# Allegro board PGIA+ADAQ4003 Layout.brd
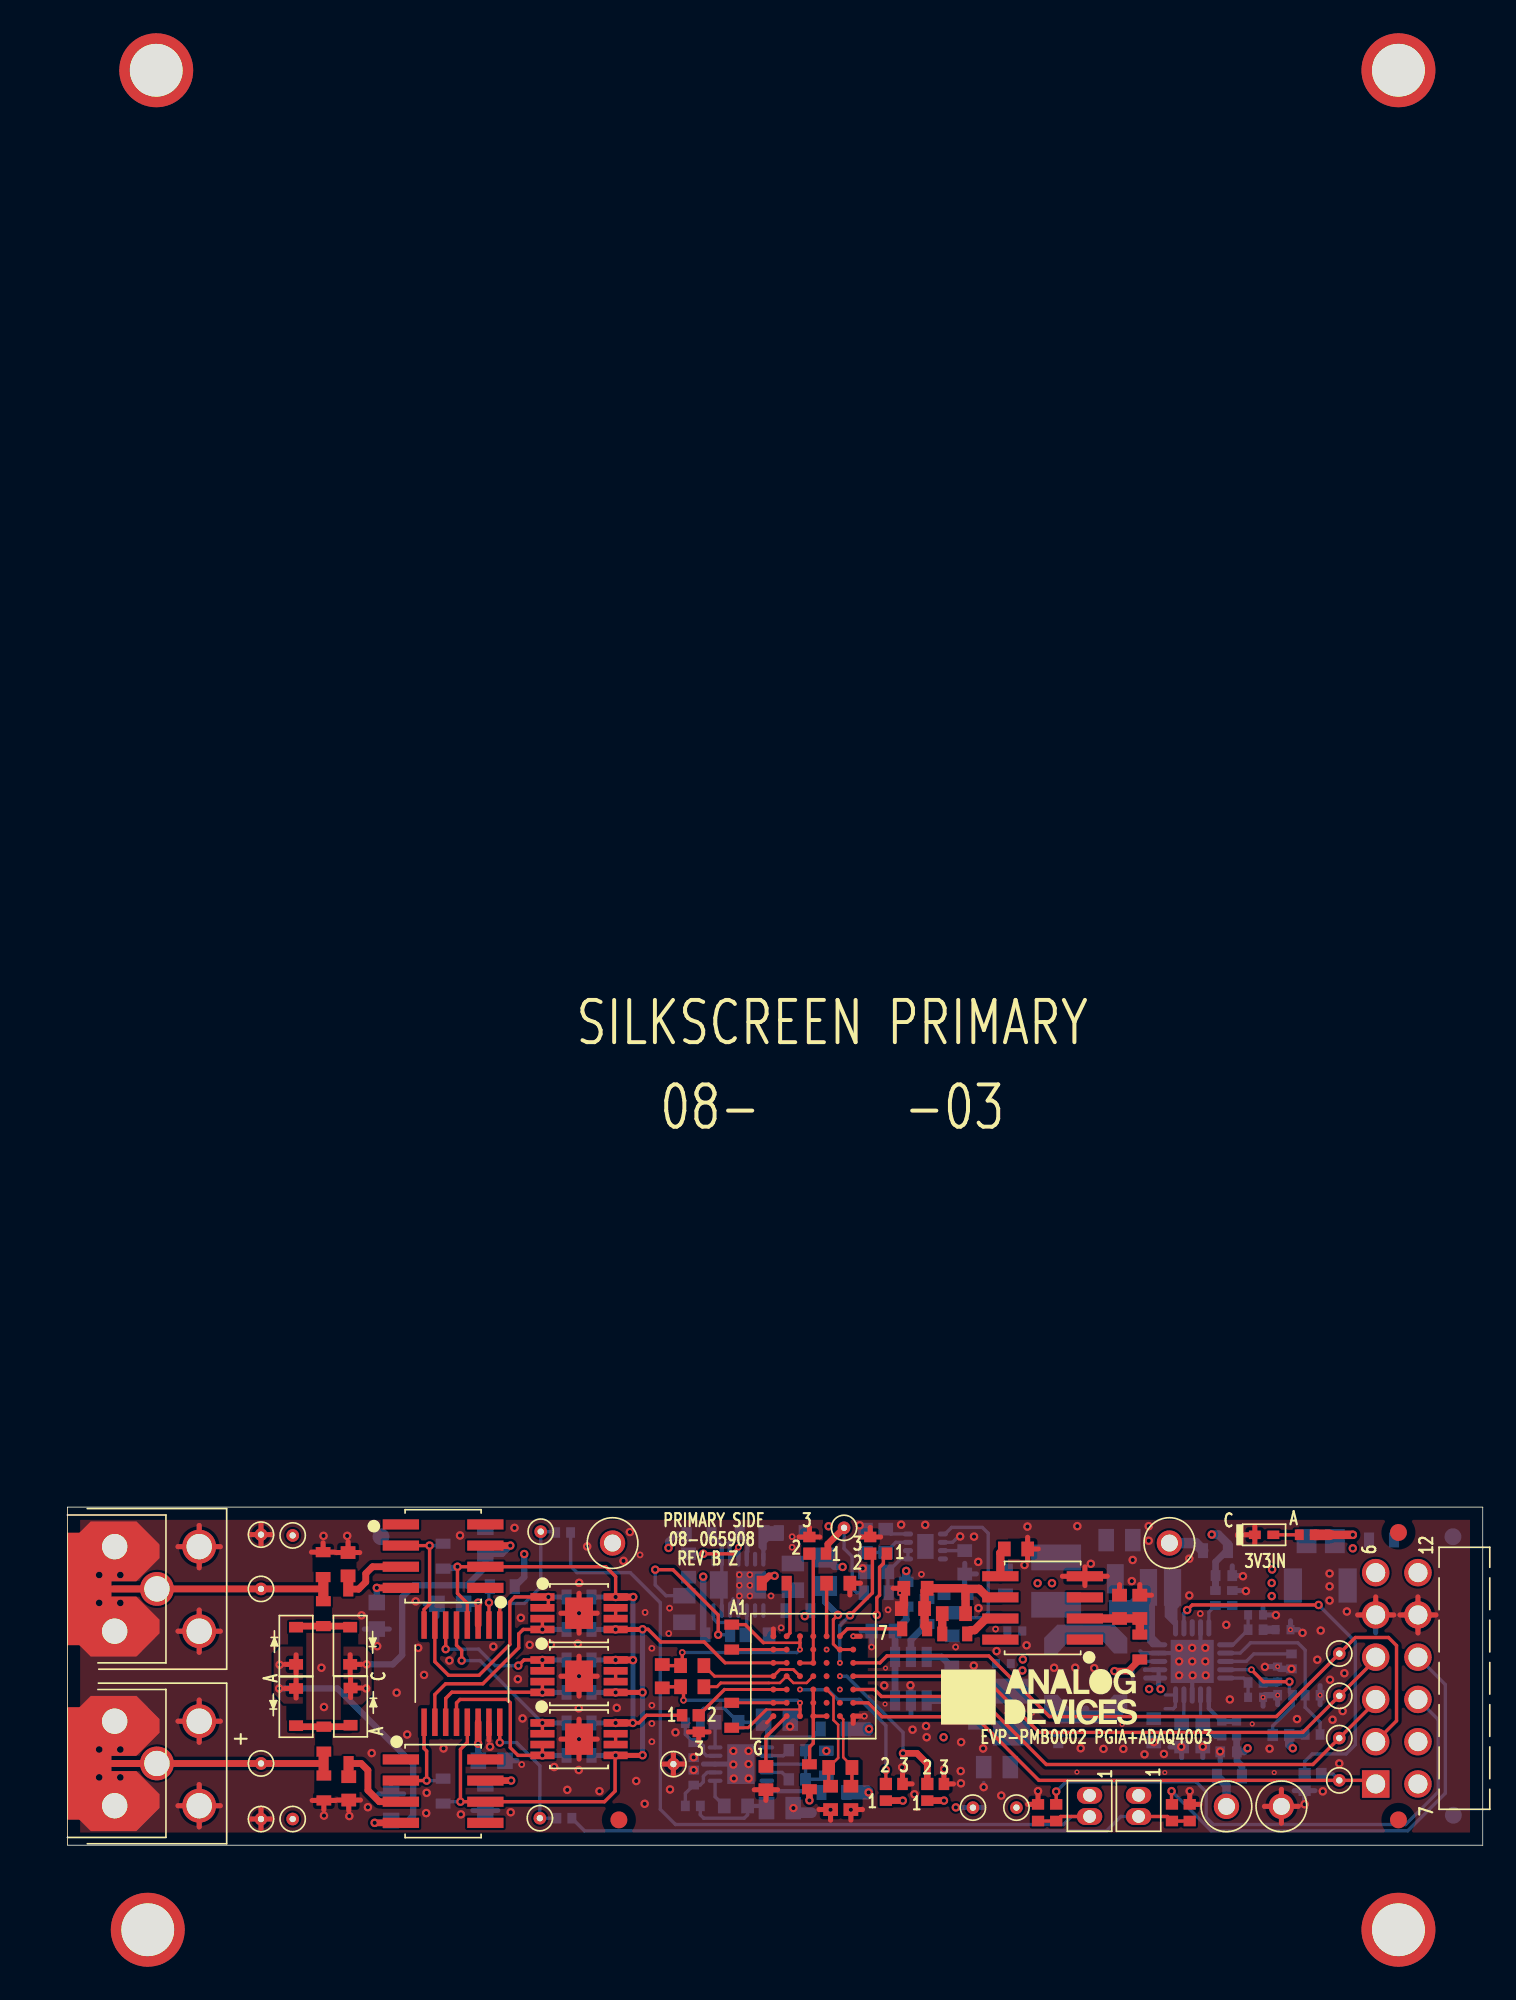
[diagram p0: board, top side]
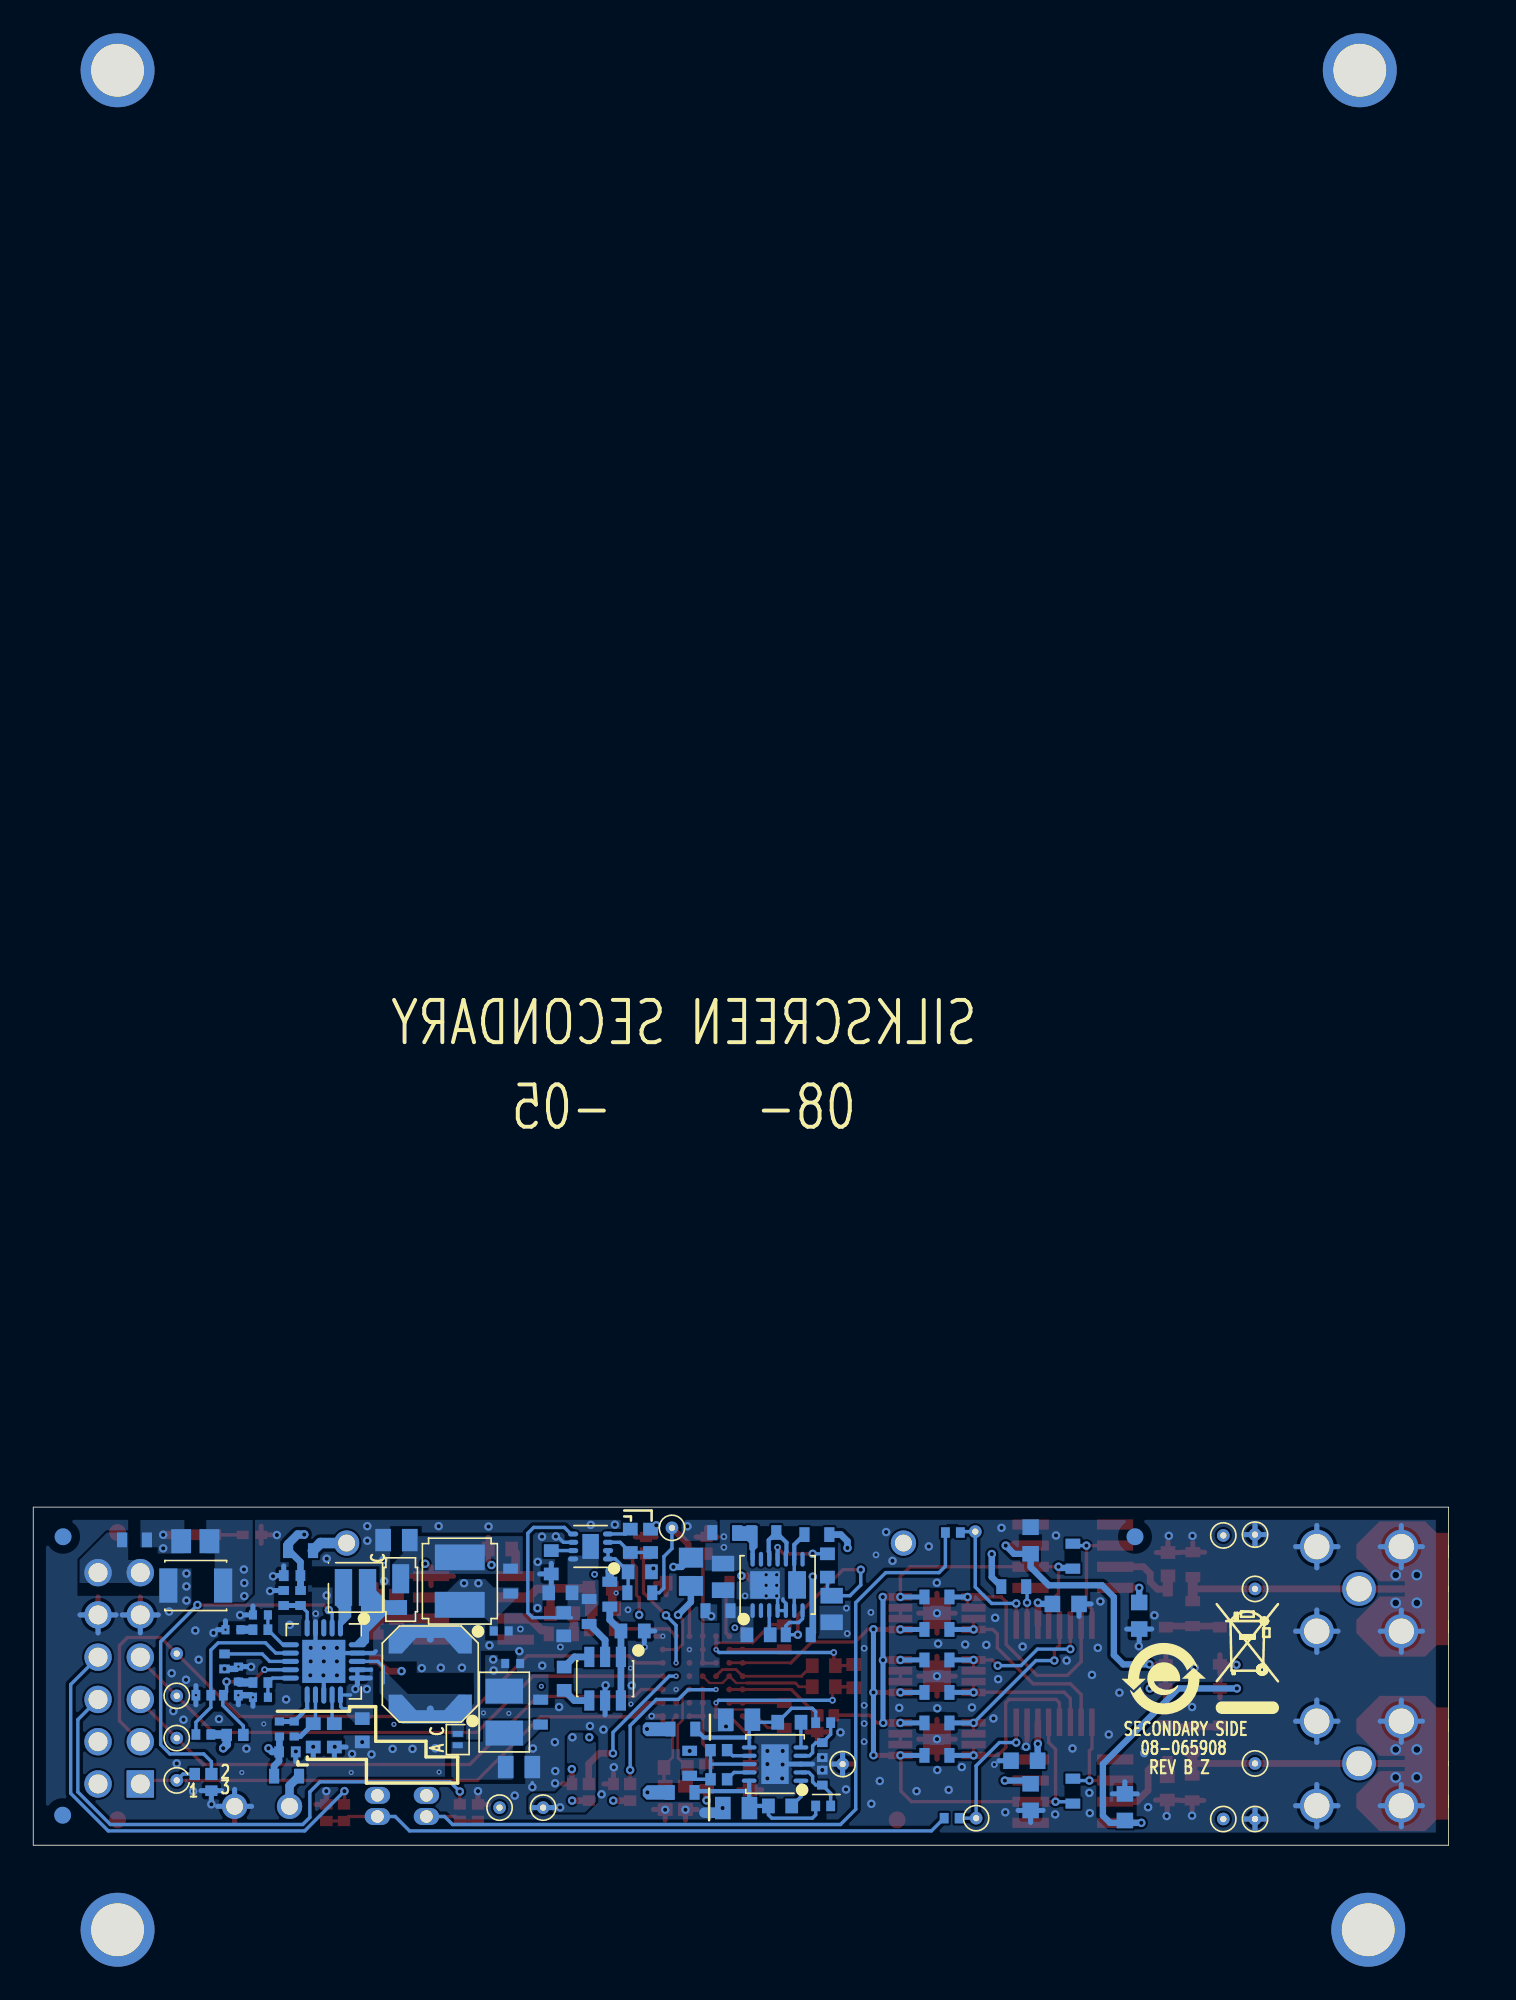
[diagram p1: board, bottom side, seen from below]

Outline 85.08 x 20.32 mm; copper layers: TOP, L2_GND, L3_PWR, BOTTOM. Coordinates in mm from the lower left corner of the outline.
Outline path: 0,20.32 0,0 85.08,0 85.08,20.32 0,20.32

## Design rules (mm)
constraint set DEFAULT: min track width 0.203

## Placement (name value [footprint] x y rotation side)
A1  ADA4627-1BRZ  [SO8]  22.58 17.37 270 top
A2  ADA4627-1BRZ  [SO8]  22.58 3.25 270 top
C1  2.2uF  [C0603]  64.46 14.33 90 top
C2  0.1uF  [C0603]  63.24 14.33 90 top
C3  TBD0603  [C0603]  57.02 17.81 0 top
C4  TBD0603  [C0603]  53.29 13.92 0 top
C5  22uF  [C1210H106]  75.31 15.61 180 bottom
C6  0.1uF  [C0603]  50.98 15.44 180 top
C7  1uF  [C0603]  66.98 6.6 90 bottom
C8  2.2uF  [C0603]  50.83 14.22 180 top
C9  10uF  [C0603]  65.3 6.91 90 bottom
C10  TBD0603  [C0603]  46.33 15.75 0 top
C11  TBD0603  [C0603]  41.99 4.04 270 top
C12  0.01uF  [C0603]  39.62 7.39 180 bottom
C13  0.01uF  [C0603]  40.18 2.36 180 bottom
C14  0.01uF  [C0603]  41.48 12.65 0 bottom
C15  0.01uF  [C0603]  37.34 16.81 270 bottom
C16  4.7uF  [C0805H60]  43.61 16.13 90 bottom
C17  4.7uF  [C0805H60]  37.08 14.2 90 bottom
C18  4.7uF  [C0805H60]  42.65 7.54 0 bottom
C19  4.7uF  [C0805H60]  42.82 2.24 0 bottom
C20  TBD0603  [C0603]  16.87 16.89 90 top
C21  TBD0603  [C0603]  16.91 3.42 270 top
C22  0.1uF  [C0603#2]  25.5 5.08 0 bottom
C23  TBD0603  [R0603]  22.58 17.37 270 bottom
C24  TBD0603  [R0603]  22.58 3.25 270 bottom
C25  0.1uF  [C0603#2]  18.59 13.79 270 bottom
C26  TBD0603  [C0603]  35.75 10.16 270 top
C27  0.1uF  [C0603#2]  23.01 14.5 180 bottom
C28  1uF  [C0603]  68.25 6.6 270 bottom
C29  0.1uF  [C0603#2]  25.12 18.31 90 bottom
C30  TBD0603  [R0603]  30.75 14.92 0 bottom
C31  TBD0603  [R0603]  30.75 12.97 0 bottom
C32  TBD0603  [C0603]  37.56 10.79 0 top
C33  TBD0603  [C0603]  37.56 9.53 0 top
C34  TBD0603  [R0603]  30.75 9.18 0 bottom
C35  TBD0603  [R0603]  30.75 11.14 0 bottom
C36  TBD0603  [R0603]  30.75 5.4 0 bottom
C37  TBD0603  [C0603]  47.09 2.84 270 top
C38  TBD0603  [R0603]  30.75 7.35 0 bottom
C39  TBD0603  [C0603]  46.46 4.67 180 top
C40  TBD0603  [C0603]  45.87 2.84 270 top
C41  TBD0402  [C0402#2]  69.52 16.21 180 bottom
C42  TBD0402  [C0402#2]  69.8 5.61 0 bottom
C43  4.7uF  [C0603]  48.62 16.43 180 bottom
C44  10uF  [C0805H60]  55.88 4.7 0 bottom
C45  1uF  [C0603]  47.97 18.3 90 bottom
C46  10uF  [C0603]  49.05 12.88 0 bottom
C47  10uF  [C0805H60]  63.24 18.34 180 bottom
C48  0.01uF  [C0603]  49.19 18.3 90 bottom
C49  1uF  [C0603]  53.16 10.01 270 bottom
C50  10uF  [C0603]  53.19 13.28 90 bottom
C51  27pF  [C0402H22]  71.42 13.84 0 bottom
C52  47pF  [C0402]  71.42 8.89 0 bottom
C53  4.7uF  [C0603]  53.39 15.18 0 bottom
C54  1500pF  [C0402]  73.07 12.95 0 bottom
C55  0.022uF  [C0402]  72.74 10.29 90 bottom
C56  1uF  [C0603]  53.94 17.01 270 bottom
C57  TBD0402  [C0402]  56.26 10.92 180 bottom
C58  TBD0402  [C0402]  56.94 12.88 0 bottom
C61  0.1uF  [C0603#2]  25.12 2.9 270 bottom
C62  0.1uF  [C0603#2]  19.46 2.29 90 bottom
CNV  TESTPAD  [TPC30D15]  76.45 3.9 0 top
D1  PD3S140-7  [POWERDI323]  62.99 15.37 270 bottom
D2  BAT54LPS  [DFN2_1X0_6]  59.56 6.35 270 bottom
D3  NSR0320MW2T1G  [SOD323-4]  16.99 11.99 90 top
D4  NSR0320MW2T1G  [SOD323-4]  13.74 11.99 270 top
D5  NSR0320MW2T1G  [SOD323-4]  17.02 8.33 270 top
D6  NSR0320MW2T1G  [SOD323-4]  13.74 8.31 90 top
DS1  APHHS1005CGCK  [LED0402_A]  71.93 18.66 0 top
E1  600OHM AT 100MEGHZ  [L0805]  45.54 16.43 90 bottom
E2  600OHM AT 100MEGHZ  [L0805]  75.34 18.28 180 bottom
GND1  TESTPAD  [TPC30D15]  11.63 1.57 0 top
GND2  TESTPAD  [TPC30D15]  11.63 18.67 0 top
GND3  TESTPAD  [TPC30D15]  36.42 4.88 0 top
J1  131-3701-301  [CNJOHNSON131-3701-301]  5.38 15.41 0 top
J2  131-3701-301  [CNJOHNSON131-3701-301]  5.38 4.91 0 top
J3  142-0761-841  [CNSMAL554W247H118]  0 15.4 180 top
J4  142-0761-841  [CNSMAL554W247H118]  0 4.91 180 top
JA0  FTS-102-01-F-S  [CNSAMTECFTS-102-01-F-S]  61.44 3 270 top
JA1  FTS-102-01-F-S  [CNSAMTECFTS-102-01-F-S]  64.39 3 270 top
JP1  3PIN_JUMPER  [3PINJUMPER_0402]  74.37 4.28 90 bottom
JP2  3PIN_JUMPER  [3PINJUMPER_0402]  37.95 7.81 90 top
JP3  3PIN_JUMPER  [3PINJUMPER_0402]  51.69 3.68 180 top
JP4  3PIN_JUMPER  [3PINJUMPER_0402]  48.26 17.53 270 top
JP5  3PIN_JUMPER  [3PINJUMPER_0402]  49.2 3.68 180 top
JP6  3PIN_JUMPER  [3PINJUMPER_0402]  44.6 17.53 270 top
L1  4.7uH  [LSMSQ79H57]  65.71 15.49 180 bottom
L2  33UH  [LSMSQ189H123]  61.21 10.29 270 bottom
L3  1.5uH  [L2520-3]  56.77 8 90 bottom
L4  2.2UH  [L1515]  59.43 15.87 270 bottom
N1V  TESTPAD  [TPC30D15]  46.68 19.08 0 top
N15V  TESTPAD  [TPC30D15]  13.54 18.62 0 top
N16V  RED  [CNKEY5001TP]  69.67 2.34 0 top
NOREF  -  []  63.44 -165.56 0 top
NOREF#2  -  []  4.83 -5.08 0 top
NOREF#3  -  []  0 20.59 0 top
NOREF#4  -  []  4.83 -5.08 0 top
NOREF#5  -  [unnamed#2]  80.01 1.52 0 top
NOREF#6  -  []  85.06 -6.73 90 top
NOREF#7  -  []  0 20.32 0 top
NOREF#8  -  []  -20.7 -48.64 0 top
NOREF#9  -  []  85.09 -10.16 90 top
NOREF#10  -  []  85.09 -10.16 0 top
NOREF#11  -  []  0 0 0 top
NOREF#12  -  []  0 40.86 0 top
NOREF#13  -  []  0 -0.03 0 top
NOREF#14  -  []  0 101.78 0 top
NOREF#15  -  []  -218.18 -201.45 0 top
NOREF#16  -  []  0 60.63 0 top
NOREF#17  -  [unnamed#2]  33.15 1.52 0 top
NOREF#18  -  [unnamed#2]  80.01 -5.08 0 top
NOREF#19  -  [unnamed#2]  4.83 -5.08 0 top
NOREF#20  -  []  0 20.58 0 top
NOREF#21  -  []  162.43 50.2 0 top
NOREF#22  -  []  0 111.76 0 top
NOREF#23  -  []  0 60.96 0 top
NOREF#24  -  []  0 111.76 0 top
NOREF#25  -  []  268.73 -83.5 0 top
NOREF#26  -  [unnamed#2]  80.01 18.8 0 top
NOREF#27  -  []  0 101.6 0 top
NOREF#28  -  []  0 81.33 0 top
NOREF#29  -  [unnamed#2]  80.01 106.68 0 top
NOREF#30  -  []  -28.18 -217.58 0 top
NOREF#31  -  []  60.96 159.38 0 top
NOREF#32  -  []  0 -10.16 0 top
NOREF#33  -  []  45.97 43.21 0 top
NOREF#34  -  []  0 -10.16 0 top
NOREF#35  -  [unnamed#2]  5.33 106.68 0 top
NOREF#36  -  []  0 40.64 0 top
NOREF#37  -  []  58.42 8.05 0 top
NOREF#38  -  []  -4.83 25.91 270 top
NOREF#39  -  []  90.16 22.21 180 top
NOREF#40  -  []  0 81.28 0 top
NOREF#41  -  []  0 10.11 0 top
NOREF#42  -  []  -7.05 -8.13 0 top
NOREF#43  -  [unnamed#2]  83.31 1.8 180 bottom
NOREF#44  -  []  17.12 10.01 180 bottom
NOREF#45  -  [unnamed#2]  18.85 18.54 180 bottom
NOREF#46  -  []  12.29 7.95 180 bottom
NOREF#47  -  [unnamed#2]  83.29 18.54 180 bottom
P1  TSW-106-25-F-D-RA  [CNHDRRA2X6H240]  78.64 3.68 90 top
P15V  TESTPAD  [TPC30D15]  13.54 1.57 0 top
P16V  RED  [CNKEY5001TP]  66.24 18.16 0 top
R1  0  [R0603]  64.46 11.91 90 top
R2  0  [R0603]  78.99 18.35 180 bottom
R3  TBD0603  [R0603]  53.34 12.7 180 top
R4  0  [R0603]  50.93 13 180 top
R5  100K  [R0402]  58.34 1.96 270 top
R6  10K  [R0402]  59.44 1.96 270 top
R7  100K  [R0402]  67.46 1.96 270 top
R8  0  [R0603]  42.48 15.75 0 top
R9  0  [R0603]  15.38 13.92 270 top
R10  0  [R0603]  15.41 6.38 90 top
R11  0  [R0603]  44.6 4.11 270 top
R12  10K  [R0402]  66.4 1.96 270 top
R13  0  [R0603]  45.62 4.93 270 bottom
R14  0  [R0603]  43.51 18.8 180 bottom
R15  0  [R0603]  37.97 18.67 0 bottom
R16  0  [R0402]  43.87 5.71 180 bottom
R17  0  [R0402]  43.87 3.96 180 bottom
R18  0  [R0603]  41.16 18.8 180 bottom
R19  698K  [R0402#2]  37.59 7.37 180 bottom
R20  200K  [R0402#2]  37.64 5.71 270 bottom
R21  0  [R0603]  43.91 14.1 0 bottom
R22  0  [R0603]  39.09 12.65 180 bottom
R23  95.3K  [R0402#2]  37.59 2.36 180 bottom
R24  1MEG  [R0603]  15.37 16.87 90 top
R25  1MEG  [R0603]  15.41 3.44 270 top
R26  200  [R0603]  16.13 15.39 0 top
R27  200  [R0603]  16.15 4.91 0 top
R28  10K  [R0603]  26.14 15.54 0 bottom
R29  200K  [R0402#2]  37.64 4.06 90 bottom
R30  0  [R0402#2]  29.79 18.8 0 bottom
R31  0  [R0402#2]  29.87 1.63 0 bottom
R32  0  [R0603]  39.93 12.51 270 top
R33  0  [R0603]  39.93 7.81 90 top
R34  2.4K  [R0402#2]  74.5 18.66 180 top
R35  30.1K  [R0402]  72.95 6.63 180 bottom
R36  18.7K  [R0402#2]  73.2 9.02 180 bottom
R37  0  [R0603]  46.02 6.98 0 bottom
R38  0  [R0603]  46.08 3.18 0 bottom
R39  0  [R0603]  54.58 8 90 bottom
R40  0  [R0603]  50.42 15.09 270 bottom
R41  249K  [R0402#2]  73.58 11.05 90 bottom
R42  3.09K  [R0402#2]  69.39 6.98 270 bottom
R43  0  [R0603]  48.62 15.18 0 bottom
R44  0  [R0603]  51.66 14.05 90 bottom
R52  12.4K  [R0402#2]  71.42 12.95 0 bottom
R53  64.9K  [R0402#2]  70.28 6.98 270 bottom
R54  3.57K  [R0402#2]  70.03 14.86 270 bottom
R55  7.68K  [R0402#2]  71.42 9.78 0 bottom
R58  68.1K  [R0402#2]  69.01 14.86 90 bottom
R60  0  [R0603]  56.39 15.87 270 bottom
R65  0  [R0603]  69.01 17.7 180 bottom
R66  0  [R0603]  69.85 4.15 180 bottom
R80  30.1K  [R0402#2]  74.85 6.65 0 bottom
R81  18.7K  [R0402#2]  74.85 9.02 0 bottom
RN1  1K/9K  [MSOP8_PAD1_88X1_68]  30.75 13.94 270 top
RN2  1K  [MSOP8_PAD1_88X1_68]  30.75 6.38 270 top
RN3  1.25K/5K  [MSOP8_PAD1_88X1_68]  30.75 10.16 270 top
SCK  TESTPAD  [TPC30D15]  76.45 8.98 0 top
SDI  TESTPAD  [TPC30D15]  76.45 11.52 0 top
SDO  TESTPAD  [TPC30D15]  76.45 6.44 0 top
TP3  BLK  [CNKEY5001TP]  72.97 2.34 0 top
TP_A0  TESTPAD  [TPC30D15]  28.45 18.85 0 top
TP_A1  TESTPAD  [TPC30D15]  28.4 1.63 0 top
U1  ADR4550BRZ  [SO8]  58.62 14.26 90 top
U2  ADAQ4003BBCZ  [BGA49H96]  44.83 10.16 270 top
U3  LT3023IDD#PBF  [DFN10_3X3_PAD2_38X1_64]  40.49 4.88 90 bottom
U4  ADP5070ACPZ-R7  [QFN20_4X4_PAD2_6X2_6]  67.61 11.05 0 bottom
U5  ADG1209YRUZ  [TSSOP16]  23.71 10.31 180 top
U6  LTC1983ES6-3#PBF  [TSOT23_6]  50.7 10.01 0 bottom
U7  ADP7185ACPZN1.0  [DFN8_2X2_PAD1_5X1]  51.57 17.96 90 bottom
U8  LT3032EDE-15#PBF  [DFN14_4X3_PAD1_78X1_65_PAD1_07X1_65]  40.33 15.65 180 bottom
UNK1V8  TESTPAD  [TPC30D15]  54.43 2.26 0 top
UNK3V3_EX  RED  [CNKEY5001TP]  32.77 18.16 0 top
UNK5V5  TESTPAD  [TPC30D15]  57.05 2.26 0 top
VIN+  TESTPAD  [TPC30D15]  11.63 4.91 0 top
VIN-  TESTPAD  [TPC30D15]  11.63 15.41 0 top

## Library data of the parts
A1 A2 = ADA46X7: Tolerance: N/A; User Part Number: UPN; alternate symbols: (); part number: ADA46X7_SM-ADA4627-1BRZ,E028104,SO8; tolerance: N/A
C1 C8 = CAP: User Part Number: UPN; Tolerance: 10; alternate symbols: C0603L; part number: CAP_SM-2.2UF,50V,10,E024995,C0603; tolerance: 10
C2 C6 = CAP: User Part Number: UPN; Tolerance: 10; alternate symbols: C0603L; part number: CAP_SM-0.1UF,50V,10,E011865,C0603; tolerance: 10
C3 C4 C10 C11 C26 C32 C33 C37 C39 C40 = CAP: User Part Number: UPN; alternate symbols: C0603L; part number: CAP_SM-TBD0603,TBD0603,TBD0603,E000382,C0603
C5 = CAP: Tolerance: 20; User Part Number: UPN; alternate symbols: (); part number: CAP_SM-22UF,25V,20,E038599,C1210H106; tolerance: 20
C7 C28 C45 C49 C56 = CAP: User Part Number: UPN; Tolerance: 10; alternate symbols: C0603L; part number: CAP_SM-1UF,16V,10,E020111,C0603; tolerance: 10
C9 = CAP: User Part Number: UPN; Tolerance: 20; alternate symbols: C0603L; part number: CAP_SM-10UF,6.3V,20,E030255,C0603; tolerance: 20
C12-C15 C48 = CAP: User Part Number: UPN; Tolerance: 5; alternate symbols: C0603L; part number: CAP_SM-0.01UF,25V,5,E012400,C0603; tolerance: 5
C16 C17 = CAP: User Part Number: UPN; Tolerance: 10; alternate symbols: C0805L; part number: CAP_SM-4.7UF,35V,10,E026260,C0805H60; tolerance: 10
C18 C19 = CAP: User Part Number: UPN; Tolerance: 10; alternate symbols: C0805L; part number: CAP_SM-4.7UF,16V,10,E033932,C0805H60; tolerance: 10
C20 C21 = CAP: User Part Number: UPN; alternate symbols: (C0603L,C0603L_ALT); part number: CAP_SM-TBD0603,TBD0603,TBD0603,E000382,C0603
C22 C25 C27 C29 C61 C62 = CAP: User Part Number: UPN; Tolerance: 10; alternate symbols: (C0603L); part number: CAP_SM-0.1UF,25V,10,E013746,C0603; tolerance: 10
C23 C24 C30 C31 C34-C36 C38 = RES: User Part Number: UPN; alternate symbols: (R0603L); part number: RES_SM-TBD0603,E004050,TBD0603,TBD0603,R0603
C41 C42 C57 C58 = CAP: User Part Number: UPN; alternate symbols: C0402L; part number: CAP_SM-TBD0402,TBD0402,TBD0402,E000381,C0402
C43 C53 = CAP: User Part Number: UPN; Tolerance: 10; alternate symbols: C0603L; part number: CAP_SM-4.7UF,6.3V,10,E030256,C0603; tolerance: 10
C44 C47 = CAP: User Part Number: UPN; Tolerance: 10; alternate symbols: C0805L; part number: CAP_SM-10UF,25V,10,E026259,C0805H60; tolerance: 10
C46 C50 = CAP: User Part Number: UPN; Tolerance: 20; alternate symbols: C0603L; part number: CAP_SM-10UF,25V,20,E023693,C0603; tolerance: 20
C51 = CAP: User Part Number: UPN; Tolerance: 5; alternate symbols: C0402L; part number: CAP_SM-27PF,25V,5,E033447,C0402H22; tolerance: 5
C52 = CAP: User Part Number: UPN; Tolerance: 5; alternate symbols: C0402L; part number: CAP_SM-47PF,50V,5,E011821,C0402; tolerance: 5
C54 = CAP: User Part Number: UPN; Tolerance: 5; alternate symbols: C0402L; part number: CAP_SM-1500PF,50V,5,E033272,C0402; tolerance: 5
C55 = CAP: User Part Number: UPN; Tolerance: 10; alternate symbols: C0402L; part number: CAP_SM-0.022UF,25V,10,E033914,C0402; tolerance: 10
CNV GND1-GND3 N1V N15V P15V SCK SDI SDO TP_A0 TP_A1 UNK1V8 UNK5V5 VIN+ VIN- = NCTESTPAD: Tolerance: N/A; User Part Number: UPN; alternate symbols: (); part number: NCTESTPAD_TH-TESTPAD,E013464,TPC30D15; tolerance: N/A
D1 = DIOSCHOTTKY: Tolerance: N/A; User Part Number: UPN; alternate symbols: (); part number: DIOSCHOTTKY_SM-PD3S140-7,60V,N/A,E017965,POWERDI323; tolerance: N/A
D2 = DIOSCHOTTKY: Tolerance: N/A; User Part Number: UPN; alternate symbols: (); part number: DIOSCHOTTKY_SM-BAT54LPS,30V,N/A,E023691,DFN2_1X0_6; tolerance: N/A
D3-D6 = DIOSCHOTTKY: Tolerance: N/A; User Part Number: UPN; alternate symbols: (); part number: DIOSCHOTTKY_SM-NSR0320MW2T1G,20V,N/A,E010784,SOD323-4; tolerance: N/A
DS1 = DIOLED: User Part Number: UPN; Tolerance: N/A; alternate symbols: (); part number: DIOLED_SM-APHHS1005CGCK,2.1V,N/A,E029804,LED0402_A; tolerance: N/A
E1 E2 = FERRITE: User Part Number: UPN; Tolerance: 25; alternate symbols: (L0805L); part number: FERRITE_SM-600OHM AT 100MEGHZ,25,E020490,L0805; tolerance: 25
J1 J2 = CNBNC5P: Tolerance: N/A; User Part Number: UPN; alternate symbols: (); part number: CNBNC5P_TH-131-3701-301,E000918,CNJOHNSON131-3701-301; tolerance: N/A
J3 J4 = CNBNC4P: Tolerance: N/A; User Part Number: UPN; alternate symbols: (); part number: CNBNC4P_SM-142-0761-841,E015238,CNSMAL554W247H118; tolerance: N/A
JA0 JA1 = CN2P: Tolerance: N/A; User Part Number: UPN; alternate symbols: (); part number: CN2P_TH-FTS-102-01-F-S,E021754,CNSAMTECFTS-102-01-F-S; tolerance: N/A
JP1-JP6 = NC3P_JMPR: User Part Number: UPN; Tolerance: N/A; alternate symbols: (); part number: NC3P_JMPR_SM-3PIN_JUMPER,E006495,3PINJUMPER_0402; tolerance: N/A
L1 = IND: Tolerance: 20; User Part Number: UPN; alternate symbols: (); part number: IND_SM-4.7UH,20,E016399,LSMSQ79H57; tolerance: 20
L2 = IND: User Part Number: UPN; Tolerance: 20; alternate symbols: (); part number: IND_SM-33UH,20,E040872,LSMSQ189H123; tolerance: 20
L3 = IND: Tolerance: 20; User Part Number: UPN; alternate symbols: (); part number: IND_SM-1.5UH,20,E011908,L2520-3; tolerance: 20
L4 = IND: User Part Number: UPN; Tolerance: 20; alternate symbols: (); part number: IND_SM-2.2UH,20,E029438,L1515; tolerance: 20
N16V P16V UNK3V3_EX = CNTP1P: Tolerance: N/A; User Part Number: UPN; alternate symbols: (); part number: CNTP1P_TH-RED,E019485,CNKEY5001TP; tolerance: N/A
P1 = CN12P: User Part Number: UPN; Tolerance: N/A; alternate symbols: (CNHDRRA2X6H240_OE); part number: CN12P_TH-TSW-106-25-F-D-RA,E018495,CNHDRRA2X6H240; tolerance: N/A
R1 R2 R4 R8-R11 R13-R15 R18 R21 R22 R32 R33 R37-R40 R43 R44 R60 R65 R66 = RES: User Part Number: UPN; Tolerance: JUMPER; alternate symbols: R0603L; part number: RES_SM-0,E006826,1/10W,JUMPER,R0603; tolerance: JUMPER
R3 = RES: User Part Number: UPN; alternate symbols: R0603L; part number: RES_SM-TBD0603,E004050,TBD0603,TBD0603,R0603
R5 R7 = RES: User Part Number: UPN; Tolerance: 5; alternate symbols: (R0402L); part number: RES_SM-100K,E003464,1/10W,5,R0402; tolerance: 5
R6 R12 = RES: User Part Number: UPN; Tolerance: 5; alternate symbols: (R0402L); part number: RES_SM-10K,E019640,1/16W,5,R0402; tolerance: 5
R16 R17 = RES: User Part Number: UPN; Tolerance: JUMPER; alternate symbols: R0603L; part number: RES_SM-0,E003438,1/10W,JUMPER,R0402; tolerance: JUMPER
R19 = RES: User Part Number: UPN; Tolerance: 1; alternate symbols: R0402L; part number: RES_SM-698K,E028557,1/10W,1,R0402; tolerance: 1
R20 R29 = RES: User Part Number: UPN; Tolerance: 1; alternate symbols: R0402L; part number: RES_SM-200K,E004033,1/10W,1,R0402; tolerance: 1
R23 = RES: User Part Number: UPN; Tolerance: 1; alternate symbols: R0402L; part number: RES_SM-95.3K,E006343,1/10W,1,R0402; tolerance: 1
R24 R25 = RES: User Part Number: UPN; Tolerance: 1; alternate symbols: (R0603L); part number: RES_SM-1MEG,E003682,1/10W,1,R0603; tolerance: 1
R26 R27 = RES: User Part Number: UPN; Tolerance: 1; alternate symbols: (R0603L); part number: RES_SM-200,E007248,1/10W,1,R0603; tolerance: 1
R28 = RES: User Part Number: UPN; Tolerance: 1; alternate symbols: (R0603L); part number: RES_SM-10K,E022442,1/4W,1,R0603; tolerance: 1
R30 R31 = RES: User Part Number: UPN; Tolerance: JUMPER; alternate symbols: (R0402L,R0402L_ALT); part number: RES_SM-0,E003438,1/10W,JUMPER,R0402; tolerance: JUMPER
R34 = RES: User Part Number: UPN; Tolerance: 1; alternate symbols: (R0402L); part number: RES_SM-2.4K,E021952,1/16W,1,R0402; tolerance: 1
R35 R80 = RES: User Part Number: UPN; Tolerance: 1; alternate symbols: R0402L; part number: RES_SM-30.1K,E010069,1/10W,1,R0402; tolerance: 1
R36 R81 = RES: User Part Number: UPN; Tolerance: 1; alternate symbols: R0402L; part number: RES_SM-18.7K,E010018,1/10W,1,R0402; tolerance: 1
R41 = RES: User Part Number: UPN; Tolerance: 1; alternate symbols: R0402L; part number: RES_SM-249K,E026055,1/16W,1,R0402; tolerance: 1
R42 = RES: User Part Number: UPN; Tolerance: 1; alternate symbols: C0402L; part number: RES_SM-3.09K,E021782,1/10W,1,R0402; tolerance: 1
R52 = RES: User Part Number: UPN; Tolerance: 1; alternate symbols: R0402L; part number: RES_SM-12.4K,E021386,1/10W,1,R0402; tolerance: 1
R53 = RES: User Part Number: UPN; Tolerance: 1; alternate symbols: C0402L; part number: RES_SM-64.9K,E010879,1/10W,1,R0402; tolerance: 1
R54 = RES: User Part Number: UPN; Tolerance: 1; alternate symbols: R0402L; part number: RES_SM-3.57K,E007344,1/10W,1,R0402; tolerance: 1
R55 = RES: User Part Number: UPN; Tolerance: 1; alternate symbols: R0402L; part number: RES_SM-7.68K,E028816,1/10W,1,R0402; tolerance: 1
R58 = RES: User Part Number: UPN; Tolerance: 1; alternate symbols: R0402L; part number: RES_SM-68.1K,E014436,1/10W,1,R0402; tolerance: 1
RN1 = RESNET_8P_4R_V7: Tolerance: 15; User Part Number: UPN; alternate symbols: (); part number: RESNET_8P_4R_V7_SM-1K/9K,E029434,4/5W,15,MSOP8_PAD1_88X1_68; tolerance: 15
RN2 = RESNET_8P_4R_V5: Tolerance: 15; User Part Number: UPN; alternate symbols: (); part number: RESNET_8P_4R_V5_SM-1K,E029308,0.8W,15,MSOP8_PAD1_88X1_68; tolerance: 15
RN3 = RESNET_8P_4R_V7: Tolerance: 15; User Part Number: UPN; alternate symbols: (); part number: RESNET_8P_4R_V7_SM-1.25K/5K,E029310,4/5W,15,MSOP8_PAD1_88X1_68; tolerance: 15
TP3 = CNTP1P: Tolerance: N/A; User Part Number: UPN; alternate symbols: (); part number: CNTP1P_TH-BLK,E019484,CNKEY5001TP; tolerance: N/A
U1 = ADR45XX: Tolerance: N/A; User Part Number: UPN; alternate symbols: (); part number: ADR45XX_SM-ADR4550BRZ,E016255,SO8; tolerance: N/A
U2 = ADAQ4003: Tolerance: N/A; User Part Number: UPN; alternate symbols: (); part number: ADAQ4003_SM-ADAQ4003BBCZ,E030724,BGA49H96; tolerance: N/A
U3 = LINLT3023: Tolerance: N/A; User Part Number: UPN; alternate symbols: (); part number: LINLT3023_SM-LT3023IDD#PBF,E030742,DFN10_3X3_PAD2_38X1_64; tolerance: N/A
U4 = ADP5070: User Part Number: UPN; Tolerance: N/A; alternate symbols: (); part number: ADP5070_SM-ADP5070ACPZ-R7,E017319,QFN20_4X4_PAD2_6X2_6; tolerance: N/A
U5 = ADG1209: Tolerance: N/A; User Part Number: UPN; alternate symbols: (); part number: ADG1209_SM-ADG1209YRUZ,E021401,TSSOP16; tolerance: N/A
U6 = ADLTC1983_X: User Part Number: UPN; Tolerance: N/A; alternate symbols: (); part number: ADLTC1983_X_SM-LTC1983ES6-3#PBF,E040601,TSOT23_6; tolerance: N/A
U7 = ADP7185: User Part Number: UPN; Tolerance: N/A; alternate symbols: (); part number: ADP7185_SM-ADP7185ACPZN1.0,E023732,DFN8_2X2_PAD1_5X1; tolerance: N/A
U8 = LINLT3032: User Part Number: UPN; Tolerance: N/A; alternate symbols: (); part number: LINLT3032_SM-LT3032EDE-15#PBF,E038249,DFN14_4X3_PAD1_78X1_65_PAD1_07X1_65; tolerance: N/A

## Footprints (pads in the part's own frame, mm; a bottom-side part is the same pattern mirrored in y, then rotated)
3PINJUMPER_0402
  rect 0.737x0.635 smd: 1(0,1.001)
  rect 0.737x0.737 smd: 2(0,0)
  rect 0.635x0.737 smd: 3(-1.001,0)
BGA49H96
  round 0.356 smd: A1(-2.4,-2.4) A2(-2.4,-1.6) A3(-2.4,-0.8) A4(-2.4,0) A5(-2.4,0.8) A6(-2.4,1.6) A7(-2.4,2.4) B1(-1.6,-2.4) B2(-1.6,-1.6) B3(-1.6,-0.8) B4(-1.6,0) B5(-1.6,0.8) B6(-1.6,1.6) B7(-1.6,2.4) C1(-0.8,-2.4) C2(-0.8,-1.6) C3(-0.8,-0.8) C4(-0.8,0) C5(-0.8,0.8) C6(-0.8,1.6) C7(-0.8,2.4) D1(0,-2.4) D2(0,-1.6) D3(0,-0.8) D4(0,0) D5(0,0.8) D6(0,1.6) D7(0,2.4) E1(0.8,-2.4) E2(0.8,-1.6) E3(0.8,-0.8) E4(0.8,0) E5(0.8,0.8) E6(0.8,1.6) E7(0.8,2.4) F1(1.6,-2.4) F2(1.6,-1.6) F3(1.6,-0.8) F4(1.6,0) F5(1.6,0.8) F6(1.6,1.6) F7(1.6,2.4) G1(2.4,-2.4) G2(2.4,-1.6) G3(2.4,-0.8) G4(2.4,0) G5(2.4,0.8) G6(2.4,1.6) G7(2.4,2.4)
C0402
  rect 0.483x0.559 smd: 1(-0.45,0) 2(0.45,0)
C0402#2
  rect 0.584x0.66 smd: 1(-0.5,0) 2(0.5,0)
C0402H22
  rect 0.483x0.559 smd: 1(-0.45,0) 2(0.45,0)
C0603
  rect 0.762x0.889 smd: 1(-0.701,0) 2(0.701,0)
C0603#2
  rect 0.94x0.991 smd: 1(-0.8,0) 2(0.8,0)
C0805H60
  rect 0.94x1.346 smd: 1(-0.8,0) 2(0.8,0)
C1210H106
  rect 1.092x2.057 smd: 1(-1.646,0) 2(1.646,0)
CNHDRRA2X6H240
  rect 1.651x1.651 hole 1.143: 1(0,0)
  round 1.651 hole 1.143: 2(2.54,0) 3(5.08,0) 4(7.62,0) 5(10.16,0) 6(12.7,0) 7(0,-2.54) 8(2.54,-2.54) 9(5.08,-2.54) 10(7.62,-2.54) 11(10.16,-2.54) 12(12.7,-2.54)
CNJOHNSON131-3701-301
  round 2.032 hole 1.524: 1(0,0) 2(-2.54,2.54) 3(2.54,2.54) 4(2.54,-2.54) 5(-2.54,-2.54)
CNKEY5001TP
  round 1.524 hole 1.016: 1(0,0)
CNSAMTECFTS-102-01-F-S
  oval 1.016x1.524 hole 0.762: 1(0,0) 2(1.27,0)
CNSMAL554W247H118
  rect 5.537x0.406 smd: 1(-2.769,0)
  rrect 5.537x3.607 smd: 2(-2.769,2.261) 3(-2.769,-2.261)
  rect 2.642x6.756 smd: 4(-1.321,0)
DFN2_1X0_6
  rect 0.356x0.61 smd: A(0.34,0) C(-0.34,0)
DFN8_2X2_PAD1_5X1
  oval 0.305x0.61 smd: 1(-0.749,-1.049) 2(-0.249,-1.049) 3(0.249,-1.049) 4(0.749,-1.049) 5(0.749,1.049) 6(0.249,1.049) 7(-0.249,1.049) 8(-0.749,1.049)
  rect 1.499x0.991 smd: PAD(0,0)
DFN10_3X3_PAD2_38X1_64
  oval 0.254x0.889 smd: 1(-1.001,-1.554) 2(-0.5,-1.554) 3(0,-1.554) 4(0.5,-1.554) 5(1.001,-1.554) 6(1.001,1.554) 7(0.5,1.554) 8(0,1.554) 9(-0.5,1.554) 10(-1.001,1.554)
  rect 2.388x1.651 smd: PAD(0,0)
DFN14_4X3_PAD1_78X1_65_PAD1_07X1_65
  oval 0.254x0.889 smd: 1(-1.501,-1.544) 2(-1.001,-1.544) 3(-0.5,-1.544) 4(0,-1.544) 5(0.5,-1.544) 6(1.001,-1.544) 7(1.501,-1.544) 8(1.501,1.544) 9(1.001,1.544) 10(0.5,1.544) 11(0,1.544) 12(-0.5,1.544) 13(-1.001,1.544) 14(-1.501,1.544)
  rect 1.778x1.651 smd: PAD1(-0.762,0)
  rect 1.067x1.651 smd: PAD2(1.171,0)
L0805
  rect 1.194x1.448 smd: 1(-0.851,0) 2(0.851,0)
L1515
  rect 1.549x2.997 smd: 1(-1.425,0) 2(1.425,0)
L2520-3
  rect 1.499x2.261 smd: 1(-1.262,0) 2(1.262,0)
LED0402_A
  rect 0.711x0.508 smd: A(0.556,0) C(-0.556,0)
LSMSQ79H57
  rect 1.041x2.21 smd: 1(-0.724,0) 2(0.724,0)
LSMSQ189H123
  custom 0.434x0.434 smd: 1(-2.103,0) 2(2.103,0)
MSOP8_PAD1_88X1_68
  rect 0.457x1.448 smd: 1(-0.975,-2.2) 2(-0.325,-2.2) 3(0.325,-2.2) 4(0.975,-2.2) 5(0.975,2.2) 6(0.325,2.2) 7(-0.325,2.2) 8(-0.975,2.2)
  rect 1.88x1.676 smd: PAD(0,0)
POWERDI323
  rect 0.864x0.737 smd: A(1.09,0)
  rect 1.753x1.016 smd: C(-0.65,0)
QFN20_4X4_PAD2_6X2_6
  oval 0.305x1.041 smd: 1(-1.001,-2.019) 2(-0.5,-2.019) 3(0,-2.019) 4(0.5,-2.019) 5(1.001,-2.019) 11(1.001,2.019) 12(0.5,2.019) 13(0,2.019) 14(-0.5,2.019) 15(-1.001,2.019)
  oval 1.041x0.305 smd: 6(2.019,-1.001) 7(2.019,-0.5) 8(2.019,0) 9(2.019,0.5) 10(2.019,1.001) 16(-2.019,1.001) 17(-2.019,0.5) 18(-2.019,0) 19(-2.019,-0.5) 20(-2.019,-1.001)
  rect 2.591x2.591 smd: PAD(0,0)
R0402
  rect 0.635x0.737 smd: 1(-0.5,0) 2(0.5,0)
R0402#2
  rect 0.533x0.635 smd: 1(-0.45,0) 2(0.45,0)
R0603
  rect 0.61x0.889 smd: 1(-0.749,0) 2(0.749,0)
SO8
  rect 0.61x2.184 smd: 1(-1.905,-2.54) 2(-0.635,-2.54) 3(0.635,-2.54) 4(1.905,-2.54) 5(1.905,2.54) 6(0.635,2.54) 7(-0.635,2.54) 8(-1.905,2.54)
SOD323-4
  rect 0.635x0.838 smd: A(1.118,0) C(-1.118,0)
TPC30D15
  round 0.762 hole 0.381: 1(0,0)
TSOT23_6
  rect 0.61x1.219 smd: 1(-0.95,-1.311) 2(0,-1.311) 3(0.95,-1.311) 4(0.95,1.311) 5(0,1.311) 6(-0.95,1.311)
TSSOP16
  rect 0.33x1.651 smd: 1(-2.276,-2.921) 2(-1.626,-2.921) 3(-0.975,-2.921) 4(-0.325,-2.921) 5(0.325,-2.921) 6(0.975,-2.921) 7(1.626,-2.921) 8(2.276,-2.921) 9(2.276,2.921) 10(1.626,2.921) 11(0.975,2.921) 12(0.325,2.921) 13(-0.325,2.921) 14(-0.975,2.921) 15(-1.626,2.921) 16(-2.276,2.921)
unnamed#2
  round 1.016 smd: (0,0)

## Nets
1V8: R8.1 R38.2(N2) UNK1V8.1
3V3EXT: P1.6 P1.12 R2.1
3V3IN: E1.2(N2) E2.1 R2.2(N2) R28.2(N2) R34.1 R40.1 UNK3V3_EX.1
5V5: JA0.1 JA1.1 JP3.1 JP4.1 JP5.1 R1.1 R11.2(N2) R37.2(N2) UNK5V5.1
AGND: C1.2(N2) C2.2(N2) C3.2(N2) C5.1 C6.2(N2) C7.1 C8.2(N2) C9.1 C10.2(N2) C11.2(N2) C16.2(N2) C17.1 C18.2(N2) C19.2(N2) C20.2(N2) C21.2(N2) C22.2(N2) C25.2(N2) C27.2(N2) C28.2(N2) C29.2(N2) C37.2(N2) C40.2(N2) C41.1 C42.1 C43.2(N2) C44.1 C45.2(N2) C46.1 C47.1 C50.1 C51.2(N2) C52.2(N2) C53.2(N2) C54.2(N2) C55.2(N2) C56.2(N2) C57.2(N2) C58.1 C61.2(N2) C62.2(N2) DS1.C GND1.1(N1) GND2.1(N1) GND3.1(N1) J1.2 J1.3 J1.4 J1.5(SH4) J2.2 J2.3 J2.4 J2.5(SH4) J3.2 J3.3 J3.4(SH3) J4.2 J4.3 J4.4(SH3) JP1.3 JP2.3 JP3.3 JP4.3 JP5.3 JP6.3 L2.1 P1.5 P1.11 R5.1 R7.1 R20.2(N2) R24.2(N2) R25.2(N2) R29.2(N2) R36.2(N2) R41.1 R54.1 R81.2(N2) RN1.PAD RN2.PAD RN3.PAD TP3.1(N1) U1.4 U2.A1 U2.A7 U2.B5 U2.E6 U2.G1 U2.G7 U3.3 U3.PAD U4.4 U4.13 U4.19 U4.PAD U5.15 U6.5 U7.6 U8.4 U8.5 U8.PAD1
P15V: A1.7 A2.7 C22.1 C29.1 C61.1 D3.C D5.C P15V.1(N1) R13.1 R21.2(N2) U5.14
P16V: P16V.1(N1) R14.1 R65.2(N2)
VIN+: A1.3 C20.1 R26.2(N2)
VIN-: A2.3 C21.1 R27.2(N2)
ADJ1: R19.2(N2) R20.1 U3.4
ADJ2: R23.2(N2) R29.1 U3.2
AFE_OUT+: A2.6 C24.2(N2) C31.2(N2) C34.2(N2) C36.2(N2) RN1.5 RN2.5 RN3.5 U2.C1 U2.C2 U5.13
AFE_OUT-: A1.6 C23.2(N2) C30.2(N2) C35.2(N2) C38.2(N2) JP2.1 RN1.8(N8) RN2.8(N8) RN3.8(N8) U5.4
CNV: CNV.1(N1) JP1.1 P1.1 U2.F7
FDAINN: C32.2(N2) U2.D1 U2.D3
FDAINP: C33.2(N2) U2.D2 U2.D4
IN1-: A1.2 C23.1 U5.8
IN2-: A2.2 C24.1 U5.9
MODE: JP5.2(COM) U2.E3
MUX_A0: JA0.2(N2) R5.2(N2) R6.2(N2) R30.2(N2)
MUX_A1: JA1.2(N2) R7.2(N2) R12.2(N2) R31.2(N2)
N1V: JP6.1 N1V.1(N1) R43.1
N3V: C50.2(N2) C53.1 R44.2(N2) U7.5 U7.8 U7.PAD
N15V: A1.4(V-) A2.4(V-) C25.1 C27.1 C62.1 D4.A(P) D6.A(P) N15V.1(N1) R22.2(N2) U5.3(VSS)
N16V: N16V.1(N1) R15.1 R66.2(N2)
OUT1_5V5: C12.1 C18.1 R19.1 R37.1 U3.6
OUT2_1V8: C13.1 C19.1 R23.1 R38.1 U3.10
OUTN: C26.2(N2) C33.1 R33.1 U2.F3 U2.G3
OUTP: C26.1 C32.1 R32.1 U2.A3 U2.B3
PD_AMP: JP4.2(COM) U2.C6
PD_REF: JP3.2(COM) U2.D6
PMOD_A0: P1.9(N9) R6.1
PMOD_A1: P1.10 R12.1
R1K1P: JP2.2(COM) U2.E1 U2.E2
REF: R4.2(N2) U2.A6
SCK: P1.4 SCK.1(N1) U2.D7
SDI: P1.2 SDI.1(N1) U2.C7
SDO: P1.3 SDO.1(N1) U2.E7
SYNC: JP1.2(COM) U4.2
UNNAMED_4_ADAQ4003_I410_ADCIN: C37.1 C39.1 U2.G6
UNNAMED_4_ADAQ4003_I410_ADCIN_1: C39.2(N2) C40.1 U2.E5
UNNAMED_4_ADAQ4003_I410_R1K: R32.2(N2) U2.B1 U2.B2
UNNAMED_4_ADAQ4003_I410_R1K_1: R33.2(N2) U2.F1 U2.F2
UNNAMED_4_ADAQ4003_I410_REFOUT: C10.1 U2.A5
UNNAMED_4_ADAQ4003_I410_VCMO: C11.1 U2.G2
UNNAMED_4_ADAQ4003_I410_VDD: R8.2(N2) U2.A2
UNNAMED_4_ADAQ4003_I410_VIO1: E1.1 U2.B6 U2.B7
UNNAMED_4_ADAQ4003_I410_VS: JP6.2(COM) U2.A4 U2.B4 U2.C3 U2.C4(VS-_4)
UNNAMED_4_ADAQ4003_I410_VS_1: R11.1 U2.E4 U2.F4 U2.G4 U2.G5
UNNAMED_4_ADG1209_I166_A0: R30.1 TP_A0.1(N1) U5.1
UNNAMED_4_ADG1209_I166_EN: R28.1 U5.2
UNNAMED_4_ADR45XX_I321_NC3: C3.1 U1.5
UNNAMED_4_ADR45XX_I321_NC4: R3.1 U1.7
UNNAMED_4_ADR45XX_I321_VIN: C1.1 C2.1 R1.2(N2) U1.2
UNNAMED_4_ADR45XX_I321_VOUT: C4.2(N2) C6.1 C8.1 R4.1 U1.6(VOUT)
UNNAMED_4_CAP_I323_N1: C4.1 R3.2(N2)
UNNAMED_4_CNBNC5P_I402_CNTR: J1.1 J3.1 R9.1 R24.1 R26.1 VIN-.1(N1)
UNNAMED_4_CNBNC5P_I403_CNTR: J2.1 J4.1 R10.1 R25.1 R27.1 VIN+.1(N1)
UNNAMED_4_DIOSCHOTTKY_I374_N: D3.A(P) D4.C R9.2(N2)
UNNAMED_4_DIOSCHOTTKY_I376_N: D5.A(P) D6.C R10.2(N2)
UNNAMED_4_NCTESTPAD_I380_N1: R31.1 TP_A1.1(N1) U5.16
UNNAMED_4_RESNET8P4RV5_I204_N6: RN2.6 RN2.7
UNNAMED_4_RESNET8P4RV7_I203_N6: RN3.6 RN3.7
UNNAMED_4_RESNET8P4RV7_I206_N6: RN1.6 RN1.7
UNNAMED_7_ADLTC1983X_I198_C: C49.1 U6.3
UNNAMED_7_ADLTC1983X_I198_C_1: C49.2(N2) U6.4
UNNAMED_7_ADLTC1983X_I198_SHDNN: C46.2(N2) R40.2(N2) U6.1 U6.6
UNNAMED_7_ADLTC1983X_I198_VOUT: R44.1 U6.2(VOUT)
UNNAMED_7_ADP5070_I184_COMP1: C51.1 R52.1 U4.6
UNNAMED_7_ADP5070_I184_COMP2: C52.1 R55.1 U4.10
UNNAMED_7_ADP5070_I184_EN1: R80.2(N2) R81.1 U4.7
UNNAMED_7_ADP5070_I184_EN2: R35.2(N2) R36.1 U4.9
UNNAMED_7_ADP5070_I184_FB1: R54.2(N2) R58.1 U4.5
UNNAMED_7_ADP5070_I184_FB2: R42.1 R53.1 U4.11
UNNAMED_7_ADP5070_I184_INBK: L1.1 U4.1
UNNAMED_7_ADP5070_I184_PVIN1: C5.2(N2) C9.2(N2) E2.2(N2) R35.1 R80.1 U4.15 U4.16 U4.17
UNNAMED_7_ADP5070_I184_SS: R41.2(N2) U4.8
UNNAMED_7_ADP5070_I184_SW1: D1.A(P) L1.2(N2) U4.20
UNNAMED_7_ADP5070_I184_SW2: D2.C L2.2(N2) U4.18
UNNAMED_7_ADP5070_I184_VREF: C28.1 R42.2(N2) U4.12
UNNAMED_7_ADP5070_I184_VREG: C7.2(N2) U4.14(VREG)
UNNAMED_7_ADP7185_I188_SENSE: C43.1 R43.2(N2) U7.1 U7.2
UNNAMED_7_ADP7185_I188_VA: C45.1 C48.1 U7.3
UNNAMED_7_ADP7185_I188_VAFB: C48.2(N2) U7.4
UNNAMED_7_ADP7185_I188_VREG: C56.1 U7.7(VREG)
UNNAMED_7_CAP_I29_N2: C44.2(N2) D2.A(P) L3.1 R39.1
UNNAMED_7_CAP_I43_N1: C55.1 R55.2(N2)
UNNAMED_7_CAP_I44_N1: C54.1 R52.2(N2)
UNNAMED_7_CAP_I46_N2: C47.2(N2) D1.C L4.1 R60.1
UNNAMED_7_CAP_I164_N1: C15.1 U8.11
UNNAMED_7_CAP_I164_N2: C15.2(N2) C17.2(N2) R22.1 U8.7
UNNAMED_7_CAP_I165_N1: C14.1 U8.3
UNNAMED_7_CAP_I165_N2: C14.2(N2) C16.1 R21.1 U8.1
UNNAMED_7_CAP_I175_N2: C12.2(N2) U3.5
UNNAMED_7_CAP_I176_N2: C13.2(N2) U3.1
UNNAMED_7_CAP_I210_N2: C41.2(N2) C58.2(N2) L4.2(N2) R58.2(N2) R60.2(N2) R65.1
UNNAMED_7_CAP_I211_N2: C42.2(N2) C57.1 L3.2(N2) R39.2(N2) R53.2(N2) R66.1
UNNAMED_7_DIOLED_I227_P: DS1.A(P) R34.2(N2)
UNNAMED_7_LINLT3023_I170_IN: R13.2(N2) R16.1 R17.1 U3.8
UNNAMED_7_LINLT3023_I170_SHDN1N: R16.2(N2) U3.7
UNNAMED_7_LINLT3023_I170_SHDN2N: R17.2(N2) U3.9(SHDN2_N)
UNNAMED_7_LINLT3032_I158_INN1: R15.2(N2) U8.6 U8.9 U8.PAD2
UNNAMED_7_LINLT3032_I158_SHDNNN: R18.2(N2) U8.10 U8.12(SHDNP_N)
UNNAMED_7_RES_I159_N2: R14.2(N2) R18.1 U8.14
X1: C38.1 RN2.1 RN2.2 U5.5
X2: C35.1 RN3.1 RN3.2 U5.6
X3: C30.1 RN1.1 RN1.2 U5.7
Y1: C36.1 RN2.3 RN2.4 U5.12
Y2: C34.1 RN3.3 RN3.4 U5.11
Y3: C31.1 RN1.3 RN1.4 U5.10

Pads without a net: A1 1 5 8; A2 1 5 8; P1 7 8; U1 1 3 8; U2 C5 D5 F5 F6; U4 3; U8 2 8 13

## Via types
v1: diameter 0.508, hole 0.254, TOP to BOTTOM, 226 vias
v2: diameter 0.406, hole 0.203, TOP to BOTTOM, 30 vias
v3: diameter 0.305, hole 0.152, TOP to BOTTOM, 24 vias
v4: diameter 0.66, hole 0.406, TOP to BOTTOM, 8 vias

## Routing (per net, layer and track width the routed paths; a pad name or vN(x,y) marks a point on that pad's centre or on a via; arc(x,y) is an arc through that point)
1V8: length 4.1
  TOP w0.399: v1(42.51,16.19) 42.18,16.19 R8.1
  L3_PWR w0.305: UNK1V8.1 55.07,2.26 ; UNK1V8.1 54.43,1.62 ; UNK1V8.1 53.79,2.26
  BOTTOM w0.305: 55.07,2.26 UNK1V8.1 53.79,2.26
  vias: v1(48.16,3.18) v1(52.67,6.49) v1(53.4,2.27)
3V3IN: length 8.6
  TOP w0.203: R34.1 75,18.66
  TOP w0.508: 75.87,18.66 v1(77.27,18.66)
  TOP w0.635: 75,18.66 75.87,18.66
  L3_PWR w0.305: 31.99,17.39 UNK3V3_EX.1 31.99,18.93
  BOTTOM w0.381: v1(27.46,17.5) 27.46,16.12 R28.2 ; v1(46.6,16.73) 46.1,16.73 E1.2
  BOTTOM w0.508: R40.1 v1(50.42,16.48)
  vias: v1(77.27,17.84)
5V5: length 16
  TOP w0.203: v1(48.65,13.84) 48.65,14.87 48.82,15.03 48.82,16.71 49.05,16.94 49.05,17.32 JP4.1
  TOP w0.399: v1(62.94,10.46) 63.76,10.46 R1.1 ; JP5.1 v1(50.21,2.68) ; JP3.1 v1(52.69,2.68) ; v1(44.6,2.69) R11.2
  L3_PWR w0.203: 48.67,13.41 48.65,13.42 v1(48.65,13.84)
  L3_PWR w0.305: 57.05,1.62 UNK5V5.1 ; UNK5V5.1 57.68,2.26 ; UNK5V5.1 56.41,2.26 ; UNK5V5.1 57.05,2.9 ; 60.42,3 JA0.1 ; JA0.1 61.44,3.76 ; JA0.1 62.46,3 ; 63.37,3 JA1.1 64.39,3.76
  vias: v1(48.18,6.98)
AGND: length 324
  TOP w0.203: 47.67,7.76 v2(47.9,7.76) ; U2.G1 42.03,7.35 ; v1(67.64,10.21) 67.61,10.24
  TOP w0.305: 6.64,7.45 J2.3 ; J2.3 7.92,8.73 ; J2.3 9.19,7.45 ; J2.3 7.92,6.18 ; 7.92,11.59 J1.4 ; J1.4 7.92,14.14 ; J1.4 9.19,12.87 ; J1.4 6.64,12.87 ; 41.99,2.7 C11.2 ; C11.2 41.29,3.34 ; C11.2 42.69,3.34 ; C20.2 16.87,18.23 ; C20.2 16.16,17.59 ; C20.2 17.57,17.59 ; 37.95,6.24 JP2.3 ; JP2.3 38.57,6.81 ; JP2.3 37.32,6.81 ; 57.72,17.1 C3.2 ; C3.2 57.72,18.51 ; C3.2 58.36,17.81 ; P1.5 78.64,14.93 ; P1.5 79.73,13.84 ; P1.5 77.56,13.84 ; 7.92,16.67 J1.3 ; J1.3 6.64,17.95 ; J1.3 7.92,19.22 ; J1.3 9.19,17.95 ; 64.46,15.67 C1.2 65.16,15.03 ; 14.67,17.61 R24.2 ; R24.2 15.37,18.18 ; R24.2 16.07,17.61 ; 35.79,4.88 GND3.1 ; GND3.1 36.42,5.51 ; GND3.1 37.06,4.88 ; GND3.1 36.42,4.24 ; 2.84,1.1 J2.5 ; J2.5 1.56,2.37 ; J2.5 4.11,2.37 ; J2.5 2.84,3.65 ; 47.79,2.14 C37.2 47.09,1.51 ; J1.5 4.11,12.87 ; J1.5 2.84,11.59 ; J1.5 2.84,14.14 ; J1.5 1.56,12.87 ; v1(30.75,13.94) 30.75,15.14 ; v1(30.75,13.94) 31.85,13.94 ; v1(30.75,13.94) 30.75,12.75 ; v1(30.75,13.94) 29.66,13.94 ; 2.84,6.18 J2.2 ; J2.2 1.56,7.45 ; J2.2 2.84,8.73 ; J2.2 4.11,7.45 ; 29.66,6.38 v1(30.75,6.38) ; v1(30.75,6.38) 30.75,7.57 ; v1(30.75,6.38) 30.75,5.18 ; v1(30.75,6.38) 31.85,6.38 ; 81.18,12.76 P1.11 ; P1.11 81.18,14.93 ; P1.11 80.1,13.84 ; P1.11 82.27,13.84 ; U1.4 61.16,16.73 ; U1.4 62.51,16.17 ; U1.4 59.81,16.17 ; U1.4 61.16,15.61 ; 11,1.57 GND1.1 ; GND1.1 11.63,0.94 ; GND1.1 11.63,2.21 ; GND1.1 12.27,1.57 ; 16.21,2.72 C21.2 ; C21.2 16.91,2.08 ; C21.2 17.61,2.72 ; 30.75,8.96 v1(30.75,10.16) ; v1(30.75,10.16) 30.75,11.36 ; v1(30.75,10.16) 31.85,10.16 ; v1(30.75,10.16) 29.66,10.16 ; 11,18.67 GND2.1 ; GND2.1 12.27,18.67 ; GND2.1 11.63,19.31 ; GND2.1 11.63,18.03 ; TP3.1 73.99,2.34 ; TP3.1 72.97,3.36 ; TP3.1 72.97,1.32 ; TP3.1 71.96,2.34 ; 68.09,2.46 R7.1 67.46,3.03 ; C2.2 63.24,15.67 ; 50.77,3.68 JP5.3 50.2,4.31 ; J2.4 9.19,2.37 ; J2.4 6.64,2.37 ; J2.4 7.92,1.1 ; J2.4 7.92,3.65 ; 15.41,2.13 R25.2 ; R25.2 14.71,2.69 ; R25.2 16.11,2.69 ; JP6.3 44.6,19.1 ; JP6.3 45.22,18.53 ; JP6.3 43.98,18.53 ; 2.84,16.67 J1.2 ; J1.2 4.11,17.95 ; J1.2 2.84,19.22 ; J1.2 1.56,17.95 ; DS1.C 71.38,19.17 ; DS1.C 71.38,18.15 ; DS1.C 70.76,18.66 ; 25.34,6.31 U5.15 ; U2.A1 42.43,12.99 ; 57.72,2.46 R5.1 58.34,3.03 ; 45.17,2.14 C40.2 45.87,1.51 ; 47.03,15.05 C10.2 47.67,15.75 ; 47.63,18.53 JP4.3 ; JP4.3 48.88,18.53 ; JP4.3 48.26,19.1 ; 49.64,15.44 C6.2 ; 47.23,7.33 U2.G7 47.67,7.76 ; 52.69,4.31 JP3.3 53.26,3.68 ; v3(47.23,12.56) 47.67,12.56
  TOP w0.508: C6.2 50.28,14.38 C8.2
  L2_GND w0.305: J1.3 7.92,19.22 ; J1.3 7.92,16.67 ; J1.3 6.64,17.95 ; J1.3 9.19,17.95 ; GND1.1 11.63,2.21 ; GND1.1 11,1.57 ; GND1.1 11.63,0.94 ; GND1.1 12.27,1.57 ; J2.4 7.92,3.65 ; J2.4 6.64,2.37 ; J2.4 9.19,2.37 ; J2.4 7.92,1.1 ; 2.84,11.59 J1.5 ; J1.5 4.11,12.87 ; J1.5 2.84,14.14 ; J1.5 1.56,12.87 ; 78.64,12.76 P1.5 ; P1.5 79.73,13.84 ; P1.5 77.56,13.84 ; P1.5 78.64,14.93 ; 71.96,2.34 TP3.1 ; TP3.1 72.97,1.32 ; TP3.1 72.97,3.36 ; TP3.1 73.99,2.34 ; J2.3 7.92,8.73 ; J2.3 9.19,7.45 ; J2.3 6.64,7.45 ; J2.3 7.92,6.18 ; 11,18.67 GND2.1 ; GND2.1 11.63,18.03 ; GND2.1 12.27,18.67 ; GND2.1 11.63,19.31 ; 1.56,2.37 J2.5 ; J2.5 2.84,3.65 ; J2.5 2.84,1.1 ; J2.5 4.11,2.37 ; 1.56,7.45 J2.2 ; J2.2 4.11,7.45 ; J2.2 2.84,8.73 ; J2.2 2.84,6.18 ; 6.64,12.87 J1.4 ; J1.4 7.92,14.14 ; J1.4 9.19,12.87 ; J1.4 7.92,11.59 ; 36.42,4.24 GND3.1 ; GND3.1 37.06,4.88 ; GND3.1 36.42,5.51 ; GND3.1 35.79,4.88 ; 81.18,12.76 P1.11 ; P1.11 82.27,13.84 ; P1.11 81.18,14.93 ; P1.11 80.1,13.84 ; 2.84,16.67 J1.2 ; J1.2 4.11,17.95 ; J1.2 2.84,19.22 ; J1.2 1.56,17.95
  L3_PWR w0.305: J2.2 2.84,8.73 ; J2.2 1.56,7.45 ; J2.2 2.84,6.18 ; J2.2 4.11,7.45 ; J1.4 7.92,14.14 ; J1.4 7.92,11.59 ; J1.4 6.64,12.87 ; P1.11 81.18,14.93 ; P1.11 82.27,13.84 ; P1.11 81.18,12.76 ; P1.11 80.1,13.84 ; GND1.1 11.63,2.21 ; GND1.1 11,1.57 ; GND1.1 12.27,1.57 ; J2.4 9.19,2.37 ; J2.4 7.92,3.65 ; J2.4 6.64,2.37 ; J2.3 7.92,8.73 ; J2.3 6.64,7.45 ; J2.3 7.92,6.18 ; 1.56,17.95 J1.2 ; J1.2 4.11,17.95 ; J1.2 2.84,19.22 ; J1.2 2.84,16.67 ; J2.5 4.11,2.37 ; J2.5 2.84,3.65 ; J2.5 1.56,2.37 ; 35.79,4.88 GND3.1 ; GND3.1 36.42,5.51 ; GND3.1 37.06,4.88 ; GND3.1 36.42,4.24 ; 6.64,17.95 J1.3 ; J1.3 7.92,16.67 ; J1.3 9.19,17.95 ; J1.3 7.92,19.22 ; 2.84,11.59 J1.5 ; J1.5 1.56,12.87 ; J1.5 2.84,14.14 ; J1.5 4.11,12.87 ; 11,18.67 GND2.1 ; GND2.1 12.27,18.67 ; GND2.1 11.63,18.03 ; 77.56,13.84 P1.5 ; P1.5 79.73,13.84 ; P1.5 78.64,14.93 ; P1.5 78.64,12.76
  BOTTOM w0.203: U7.6 53.21,18.21 53.56,18.56 v1(53.66,18.56) ; v1(71.98,10.72) 72,10.74 72.21,10.74 ; 55.08,3.77 v1(55.08,3.49) ; U8.PAD1 40.33,14.88 U8.4 U8.5 39.83,14.53 40.01,14.71 40.01,14.81
  BOTTOM w0.254: v1(67.61,11.05) 67.11,11.55 U4.19 64.6,11.55 64.49,11.66 ; v1(67.61,11.05) U4.13 ; v1(67.61,11.05) 68.11,11.55 U4.4
  BOTTOM w0.305: 72.21,10.74 v3(72.74,10.74) ; GND3.1 36.42,5.51 ; GND3.1 37.06,4.88 ; GND3.1 36.42,4.24 ; J2.3 7.92,8.73 ; J2.3 7.92,6.18 ; J2.3 9.19,7.45 ; J2.3 6.64,7.45 ; 71.87,8.35 v3(71.87,8.89) ; 7.92,16.67 J1.3 ; J1.3 9.19,17.95 ; J1.3 6.64,17.95 ; J1.3 7.92,19.22 ; 73.75,3.28 JP1.3 ; JP1.3 74.37,2.71 ; JP1.3 75,3.28 ; 25.12,1.37 C61.2 ; C61.2 24.37,2.1 ; C61.2 25.87,2.1 ; GND1.1 11.63,2.21 ; GND1.1 11,1.57 ; GND1.1 12.27,1.57 ; GND1.1 11.63,0.94 ; C62.2 19.46,3.81 ; C62.2 20.21,3.09 ; C62.2 18.7,3.09 ; J1.5 2.84,14.14 ; J1.5 2.84,11.59 ; J1.5 1.56,12.87 ; J1.5 4.11,12.87 ; 48.35,12.18 C46.1 47.71,12.88 ; 68.25,5.27 C28.2 ; 38.23,4.88 U3.3 39.63,4.88 ; 72.37,13.84 C51.2 71.87,14.38 ; 66.28,5.9 C7.1 66.98,5.27 ; 7.92,1.1 J2.4 ; J2.4 6.64,2.37 ; J2.4 9.19,2.37 ; J2.4 7.92,3.65 ; 1.56,2.37 J2.5 ; J2.5 2.84,1.1 ; J2.5 4.11,2.37 ; J2.5 2.84,3.65 ; J1.2 2.84,19.22 ; J1.2 4.11,17.95 ; J1.2 2.84,16.67 ; J1.2 1.56,17.95 ; 75.3,9.59 v3(75.3,9.02) 75.3,8.44 ; TP3.1 73.99,2.34 ; TP3.1 71.96,2.34 ; TP3.1 72.97,3.36 ; 2.84,6.18 J2.2 ; J2.2 2.84,8.73 ; J2.2 1.56,7.45 ; J2.2 4.11,7.45 ; P1.11 82.27,13.84 ; P1.11 81.18,12.76 ; P1.11 80.1,13.84 ; 78.64,12.76 P1.5 ; P1.5 79.73,13.84 ; P1.5 77.56,13.84 ; 50.7,9.56 U6.5 50.7,7.83 ; 7.92,11.59 J1.4 ; J1.4 9.19,12.87 ; J1.4 7.92,14.14 ; J1.4 6.64,12.87 ; GND2.1 12.27,18.67 ; GND2.1 11.63,19.31 ; GND2.1 11.63,18.03 ; GND2.1 11,18.67 ; 70.02,16.79 C41.1 70.57,16.21 ; 17.84,12.99 C25.2 ; C25.2 19.34,12.99 ; C25.2 18.59,12.27 ; 53.94,15.67 C56.2 ; C56.2 54.64,16.3 ; C56.2 53.94,16.94 ; R54.1 70.6,15.31 ; 73.52,13.49 v3(73.52,12.95) 74.02,12.95 ; 69.3,5.03 C42.1 ; 22.21,13.75 C27.2 21.49,14.5 ; 72.75,8.44 v3(72.75,9.02) ; C22.2 27.03,5.08
  BOTTOM w0.381: v1(73.58,10.6) 72.88,10.6 v3(72.74,10.74) ; v3(71.87,8.89) 72,9.02 v3(72.75,9.02)
  BOTTOM w0.635: C19.2 43.9,1.96 44.73,1.96
  vias: v1(15.27,10.67) v1(15.39,18.59) v1(15.42,8.31) v1(15.42,1.78) v1(16.81,18.59) v1(16.94,1.75) v1(17.68,13.82) v1(18.06,2.29) v1(18.29,5.54) v1(18.62,11.96) v1(19.79,9.17) v1(20.42,6.65) v1(20.93,14.66) v1(21.08,11.86) v1(21.44,10.24) v1(21.56,1.93) v1(21.59,3.15) v1(22.61,5.82) v1(22.96,11.1) v1(23.6,18.62) v1(23.65,1.85) v1(25.4,5.92) v1(25.6,11.94) v1(26.64,1.98) v1(26.87,19.08) v1(27.07,9.98) v1(27.25,13.67) v1(27.36,7.62) v1(27.79,12.04) v1(28.65,8.28) v1(29.06,12.06) v1(29.26,4.7) v1(30.05,3.33) v1(30.76,15.77) v1(30.68,12.12) v1(30.73,8.23) v1(30.73,4.52) v1(31.24,17.96) v1(31.98,3.25) v1(33.02,8.26) v1(33.43,17.09) v1(33.81,18.82) v1(34.19,3.86) v1(34.7,2.49) v1(36.22,3.35) v1(36.55,6.78) v1(37.64,5.28) v1(37.64,4.52) v1(40.03,5.66) v1(40.03,4.85) v1(40.06,4.01) v1(40.94,5.66) v1(40.94,4.88) v1(40.94,4.01) v1(43.43,7.14) v1(43.64,2.24) v1(45.87,2.13) v1(47.09,2.13) v1(47.62,19.23) v1(47.8,16.64) v1(49.1,9.6) v1(50.11,19.27) v1(50.18,4.69) v1(50.67,9.61) v1(50.8,6.95) v1(50.91,3.06) v1(51.56,19.25) v1(51.61,7.16) v1(51.65,6.49) v1(52.7,4.57) v1(53.47,8.31) v1(53.72,6.2) v1(53.7,4.46) v1(53.71,3.72) v1(54.5,18.55) v1(54.48,10.79) v1(54.75,17.03) v1(54.76,14.25) v1(55.04,5.82) v1(55.85,11.67) v1(56.13,2.98) v1(57.53,16.84) v1(57.66,12.01) v1(57.71,19.15) v1(58.34,3.25) v1(59.31,10.67) v1(60.58,10.67) v1(60.71,19.18) v1(60.91,5.83) v1(61.52,16.92) v1(61.72,10.64) v1(62.28,5.79) v1(63.47,5.79) v1(64.03,17.15) v1(63.98,15.87) v1(64.74,5.46) v1(65,19.18) v1(65,18.3) v1(65.3,6.2) v1(65.91,5.49) v1(66.82,11.86) v1(66.82,11.05) v1(66.82,10.21) v1(66.95,5.92) v1(67.44,17.22) v1(67.44,15.01) v1(67.46,3.25) v1(67.61,11.86) v1(68.25,5.92) v1(68.4,11.86) v1(68.4,11.05) v1(68.43,10.21) v1(69.29,5.64) v1(69.66,13.25) v1(69.88,8.76) v1(70.43,18.64) v1(70.66,16.17) v1(70.84,15.28) v1(72.26,5.8) v1(72.64,13.83) v1(73.91,7.58) v1(74.24,12.76) v1(74.37,2.46) v1(75.13,11.15) v1(75.34,12.9) v1(75.46,3.24) v1(75.87,16.33) v1(75.87,15.56) v1(75.87,14.71) v1(75.9,9.94) v1(76.05,7.54) v1(76.45,4.91) v1(76.66,8.06) v1(76.76,10.34) v1(76.91,14.05) v2(27.3,4.85) v2(34.42,17.45) v2(34.72,14) v2(35.13,11.84) v2(35.13,8.41) v2(35.13,7.32) v2(35.13,6.22) v2(36.14,12.73) v2(36.2,14.25) v2(40.39,16.26) v2(40.39,15.62) v2(40.39,14.99) v2(41.02,16.26) v2(41.02,15.62) v2(41.02,14.99) v2(42.29,14.99) v2(42.9,13.07) v2(43.56,18.54) v2(43.56,17.91) v2(48.34,11.91) v2(49.33,14.15) v2(51.33,16.28) v2(53.39,11.91) v2(55.79,12.99) v2(68.1,13.92) v3(45.63,11.76) v3(46.43,9.36) v3(49.17,10.64) v3(49.15,8.48) v3(50.04,15.16) v3(54.53,9.55) v3(56.49,7.92) v3(58.01,7.95) v3(60.68,4.39) v3(63.4,7.26) v3(65.96,4.37) v3(71.22,7.29) v3(72.54,4.37) v4(1.9,16.24) v4(1.9,14.56) v4(1.9,5.75) v4(1.9,4.08) v4(3.17,16.24) v4(3.17,14.56) v4(3.17,5.75) v4(3.17,4.08)
P15V: length 29.1
  TOP w0.305: D3.C 16.99,11.45 ; D3.C 17.67,10.87 ; D3.C 16.99,10.3 ; 17.02,8.87 D5.C ; D5.C 17.69,9.45 ; D5.C 17.02,10.02
  TOP w0.399: U5.14 v1(24.69,6.1)
  TOP w0.406: A1.7 v1(26.62,18.01) ; A2.7 v1(26.67,3.89)
  L3_PWR w0.508: P15V.1 13.54,3.68 15.16,5.31
  BOTTOM w0.381: v1(17.98,10.87) 19.56,10.87 20.12,11.43 20.12,14.91 20.83,15.62 24.03,15.62 25.12,16.71 C29.1 26.12,17.51 v1(26.62,18.01) ; C61.1 25.31,3.89 v1(26.67,3.89) ; C22.1 24.7,6.08
  BOTTOM w0.399: 24.7,6.08 v1(24.69,6.1)
  vias: v1(17.96,9.42) v1(44.32,13.77) v1(45.62,5.66)
P16V: length 5.3
  L3_PWR w0.305: P16V.1 67.26,18.16 ; P16V.1 66.24,19.18 ; P16V.1 66.24,17.14
  BOTTOM w0.635: P16V.1 67.81,18.16 68.26,17.71 R65.2
  vias: v1(45.76,19.17)
VIN+: length 4.8
  TOP w0.406: A1.3 18.34,16.74 17.93,16.33 17.93,15.82 17.5,15.39 R26.2 16.87,15.41 C20.1
VIN-: length 5.6
  TOP w0.406: C21.1 16.91,4.9 R27.2 17.65,4.91 18.06,4.51 18.06,3.3 18.75,2.62 A2.3
ADJ1: length 3.3
  BOTTOM w0.203: R19.2 37.14,6.66 R20.1 38.03,6.16 38.23,5.97 38.23,5.56 38.41,5.38 U3.4
ADJ2: length 3.3
  BOTTOM w0.203: R23.2 37.14,3.11 R29.1 38.03,3.61 38.23,3.81 38.23,4.15 38.46,4.38 U3.2
AFE_OUT+: length 44
  TOP w0.178: U2.C2 U2.C1 39.54,10.96
  TOP w0.203: 39.54,10.96 38.28,12.22 35.66,12.22 34.9,12.98 v1(34.57,12.98) ; U5.13 24.04,6.18 23.62,5.77 v1(23.62,2.62) A2.6 32.28,2.62 32.92,3.25 32.92,5.37 v1(32.95,5.4)
  TOP w0.305: v1(34.57,12.98) 34.56,12.97 v1(32.95,12.97) ; v1(32.95,5.4) 34.56,5.4 v1(34.57,5.41) ; v1(32.95,9.18) v1(34.57,9.18)
  BOTTOM w0.203: C24.2 22.69,2.62 v1(23.62,2.62)
  BOTTOM w0.305: v1(34.57,5.41) v1(34.57,9.18) v1(34.57,12.98) ; C31.2 v1(32.95,12.97) ; C34.2 v1(32.95,9.18) ; C36.2 v1(32.95,5.4)
AFE_OUT-: length 33.9
  TOP w0.203: JP2.1 34.81,7.81 34.35,7.35 v1(33.99,7.35) ; U5.4 24.04,14.55 23.44,15.14 v1(23.44,16.74) A1.6 32.36,16.74 32.95,16.15 v1(32.95,14.92)
  TOP w0.406: v1(34,11.13) 33.99,11.14 v1(32.95,11.14) ; v1(32.95,7.35) v1(33.99,7.35) ; v1(32.95,14.92) v1(34.01,14.92)
  BOTTOM w0.305: C30.2 v1(32.95,14.92) ; v1(33.99,7.35) 34,7.36 v1(34,11.13) 34,14.9 v1(34.01,14.92) ; C35.2 v1(32.95,11.14) ; C38.2 v1(32.95,7.35)
  BOTTOM w0.381: v1(23.44,16.74) 23.37,16.66 22.62,16.66 C23.2
CNV: length 34.7
  TOP w0.203: U2.F7 48.13,8.56 48.97,7.72 54.57,7.72 58.39,3.9 CNV.1 78.43,3.9 P1.1
  BOTTOM w0.203: JP1.1 76.07,4.28 CNV.1
FDAINN: length 6.4
  TOP w0.178: U2.D3 43.63,10.56 42.83,10.56 U2.D1 38.89,10.16 C32.2
FDAINP: length 7.2
  TOP w0.152: U2.D4 44.43,9.75 43.64,9.75 U2.D2 42.83,9.75 42.16,9.75
  TOP w0.178: C33.2 39.04,9.53 39.27,9.75 42.16,9.75
IN1-: length 7.5
  TOP w0.203: A1.2 v1(21.77,18.01) 21.77,14.5 21.44,14.17 U5.8
  BOTTOM w0.203: C23.1 22.47,18.01 v1(21.77,18.01)
IN2-: length 6.2
  TOP w0.203: A2.2 v1(21.59,3.89) 21.59,5.66 21.44,5.82 U5.9
  BOTTOM w0.203: v1(21.59,3.89) 22.47,3.89 C24.1
MODE: length 9.6
  TOP w0.203: JP5.2 v1(49.2,4.52)
  BOTTOM w0.203: v1(49.2,4.52) 49.2,7.19 47.62,8.76 46.3,8.76 45.72,9.35 44.05,9.35 v3(44.03,9.36)
MUX_A0: length 50.3
  TOP w0.203: JA0.2 59.71,1.73 R6.2 R5.2
  BOTTOM w0.203: R30.2 30.24,16.77 30.63,16.38 33.83,16.38 35.64,14.58 35.64,2.16 36.55,1.24 59.87,1.24 60.35,1.73 JA0.2
MUX_A1: length 37.9
  TOP w0.203: JA1.2 66.12,1.73 R12.2 R7.2
  BOTTOM w0.203: JA1.2 63.32,1.73 62.46,0.86 31.08,0.86 R31.2
N1V: length 6.6
  TOP w0.399: JP6.1 45.71,17.63 45.71,18.1 N1V.1
  BOTTOM w0.203: N1V.1 46.68,17.83 47.17,17.35 47.17,15.46 47.45,15.18 R43.1
N3V: length 10.6
  BOTTOM w0.203: 52.72,13.68 55.06,13.68 55.35,13.97 55.35,18.75 55,19.1 53.15,19.1 52.76,18.71 U7.5
N15V: length 32.9
  TOP w0.305: 13.07,10.87 D4.A ; D4.A 13.74,11.45 ; D4.A 13.74,10.3 ; D6.A 13.74,10 ; D6.A 13.07,9.42 ; D6.A 13.74,8.85
  TOP w0.399: U5.3 v1(24.69,14.58)
  TOP w0.406: A1.4 v1(18.59,15.47) ; A2.4 v1(18.47,1.35)
  L3_PWR w0.508: N15V.1 13.54,14.86 13.51,14.83
  BOTTOM w0.381: v1(24.69,14.58) 24.61,14.5 C27.1 ; C25.1 v1(18.59,15.47) ; v1(12.73,9.42) 16.23,9.42 20.78,4.88 20.78,1.78 20.35,1.35 19.32,1.35 ; v1(18.47,1.35) 19.32,1.35 ; 19.32,1.35 C62.1
  BOTTOM w0.399: v1(38.21,16.14) 38.21,12.77 R22.2
  vias: v1(12.75,10.85)
N16V: length 6.8
  L3_PWR w0.305: 69.67,1.32 N16V.1 ; N16V.1 70.69,2.34 ; N16V.1 68.65,2.34
  BOTTOM w0.399: R15.1 36.53,18.67 36.13,18.27 v1(36.13,17.87)
  BOTTOM w0.508: R66.2 69.67,3.58 N16V.1
OUT1_5V5: length 10.1
  BOTTOM w0.203: 41.85,7.39 C18.1 ; 41.85,7.39 C12.1 39.49,8.23 38.24,8.23 38.04,8.03 R19.1 ; 41.85,7.39 42.04,7.2 U3.6
  BOTTOM w0.254: R37.1 44.77,6.48 42.04,6.48
OUT2_1V8: length 10.2
  BOTTOM w0.203: R23.1 38.04,1.83 38.24,1.63 40.68,1.63 40.88,1.83 C13.1
  BOTTOM w0.254: C13.1 41.9,2.36 C19.1 42.04,2.25 42.04,3.25 ; 42.04,3.25 45.25,3.25 R38.1 ; 42.04,3.25 U3.10
OUTN: length 14.4
  TOP w0.127: 44.03,8.15 42.01,8.15
  TOP w0.178: 42.01,8.15 40.92,7.06 R33.1
  TOP w0.203: v2(37.03,8.71) 37.03,9.35 C33.1 35.82,9.53 C26.2 ; v3(44.03,8.56) U2.G3
  BOTTOM w0.203: v3(44.03,8.56) 43.88,8.71 v2(37.03,8.71)
OUTP: length 14.5
  TOP w0.152: 44.03,12.17 41.83,12.17
  TOP w0.203: C26.1 35.82,10.79 C32.1 36.96,10.9 v2(36.96,11.58) ; 41.83,12.17 40.74,13.26 R32.1 ; U2.A3 v3(44.03,11.76)
  BOTTOM w0.203: v3(44.03,11.76) 43.86,11.58 v2(36.96,11.58)
PD_AMP: length 7.4
  TOP w0.203: v1(47.04,13.82) 48.39,15.16 48.39,17.4 JP4.2
  BOTTOM w0.203: v1(47.04,13.82) 46.43,13.21 v3(46.43,10.96)
PD_REF: length 9.4
  TOP w0.399: JP3.2 51.69,4.9 51.06,5.52 v1(50.23,5.52)
  BOTTOM w0.203: v1(50.23,5.52) 50.23,6.78 46.85,10.16 v3(46.43,10.16)
PMOD_A0: length 32.8
  TOP w0.203: v1(59.44,3.23) R6.1
  BOTTOM w0.203: v1(59.44,3.23) 60.02,3.81 67.85,3.81 68.45,3.2 68.45,1.67 68.88,1.24 80.44,1.24 82.4,3.2 82.4,7.55 P1.9
PMOD_A1: length 28.1
  TOP w0.203: R12.1 66.37,2.48 v1(66.37,3.25)
  BOTTOM w0.203: v1(66.37,3.25) 68.76,0.86 80.57,0.86 82.83,3.12 82.83,9.66 P1.10
R1K1P: length 5.9
  TOP w0.178: 39.5,9.36 U2.E1 U2.E2
  TOP w0.203: JP2.2 39.5,9.36
REF: length 3.9
  TOP w0.203: R4.2 46.88,13 U2.A6
SCK: length 34.8
  TOP w0.203: P1.4 78.64,11.17 SCK.1 74.26,6.78 58.41,6.78 55.03,10.16 U2.D7
SDI: length 42.8
  TOP w0.203: U2.C7 48.84,10.96 49.26,11.38 55.38,11.38 59.03,7.73 72.67,7.73 SDI.1 77.42,12.48 79.41,12.48 79.9,12 79.9,7.48 P1.2
SDO: length 35
  TOP w0.203: P1.3 78.64,8.63 SDO.1 74.87,4.85 58.84,4.85 54.75,8.94 48.93,8.94 48.51,9.36 U2.E7
SYNC: length 22.7
  TOP w0.203: v1(67.31,14.14) 67.61,14.44 v1(75.21,14.44)
  BOTTOM w0.203: JP1.2 74.37,5.03 74.83,5.49 76.86,5.49 77.42,6.04 77.42,12.23 v1(75.21,14.44) ; v1(67.31,14.14) 67.11,13.94 U4.2
UNNAMED_4_ADAQ4003_I410_ADCIN: length 4.5
  TOP w0.152: U2.G6 46.63,7.56 46.63,5.28 47.16,4.76 C39.1
  TOP w0.203: C37.1 47.16,3.61 C39.1
UNNAMED_4_ADAQ4003_I410_ADCIN_1: length 6.4
  TOP w0.152: U2.E5 46.05,8.95 46.05,7.52 46.33,7.24 46.33,5.25 C39.2
  TOP w0.178: 45.76,4.5 C39.2
  TOP w0.203: C40.1 45.76,3.66 45.76,4.5
UNNAMED_4_ADAQ4003_I410_R1K: length 3.3
  TOP w0.178: U2.B2 U2.B1 R32.2
UNNAMED_4_ADAQ4003_I410_R1K_1: length 3.3
  TOP w0.178: R33.2 U2.F1 U2.F2
UNNAMED_4_ADAQ4003_I410_REFOUT: length 3.2
  TOP w0.203: U2.A5 45.63,15.75 C10.1
UNNAMED_4_ADAQ4003_I410_VCMO: length 3.5
  TOP w0.203: U2.G2 41.99,6.51 C11.1
UNNAMED_4_ADAQ4003_I410_VDD: length 3.4
  TOP w0.203: R8.2 43.43,15.55 43.43,12.76 U2.A2
UNNAMED_4_ADAQ4003_I410_VIO1: length 5.3
  TOP w0.178: v1(46.32,13.84) 46.03,13.56 46.03,12.09 46.37,11.76 U2.B6 U2.B7
  BOTTOM w0.381: v1(46.32,13.84) 45.54,14.62 E1.1
UNNAMED_4_ADAQ4003_I410_VS: length 7.5
  TOP w0.178: U2.C3 44.05,10.95 44.82,10.95 U2.C4 U2.B4 U2.A4
  TOP w0.203: U2.A4 44.83,17.29 JP6.2
UNNAMED_4_ADAQ4003_I410_VS_1: length 5.4
  TOP w0.203: U2.E4 U2.F4 U2.G4 ; U2.G4 44.83,6.13 44.62,5.91 44.62,4.88 R11.1 ; U2.G4 U2.G5
UNNAMED_4_ADG1209_I166_A0: length 8.4
  TOP w0.203: U5.1 v1(25.99,14.53)
  BOTTOM w0.203: v1(25.99,14.53) 27.46,14.53 28.45,15.52 TP_A0.1 29.29,18.85 R30.1
UNNAMED_4_ADG1209_I166_EN: length 2.3
  TOP w0.201: U5.2 v1(25.34,14.58)
  BOTTOM w0.203: v1(25.34,14.58) 25.34,15.49 R28.1
UNNAMED_4_ADR45XX_I321_NC3: length 1.7
  TOP w0.5: U1.5 56.08,17.57 C3.1
UNNAMED_4_ADR45XX_I321_NC4: length 2.4
  TOP w0.5: U1.7 55.23,13.63 54.53,12.93 54.32,12.93 R3.1
UNNAMED_4_ADR45XX_I321_VIN: length 4.3
  TOP w0.5: U1.2 C2.1 C1.1 R1.2
UNNAMED_4_ADR45XX_I321_VOUT: length 8.7
  TOP w0.508: 53.99,15.41 C4.2 ; 53.99,15.41 54.8,15.41 55.31,14.9 U1.6 ; 53.99,15.41 53.95,15.44 C6.1 51.53,15.29 C8.1 51.53,13.15 R4.1
UNNAMED_4_CAP_I323_N1: length 1.2
  TOP w0.5: R3.2 52.59,12.7 C4.1
UNNAMED_4_CNBNC5P_I402_CNTR: length 14.1
  TOP w0.406: R26.1 R9.1 ; R26.1 15.38,16.1 R24.1 ; R26.1 15.37,15.41 VIN-.1 J1.1 5.37,15.4 J3.1
